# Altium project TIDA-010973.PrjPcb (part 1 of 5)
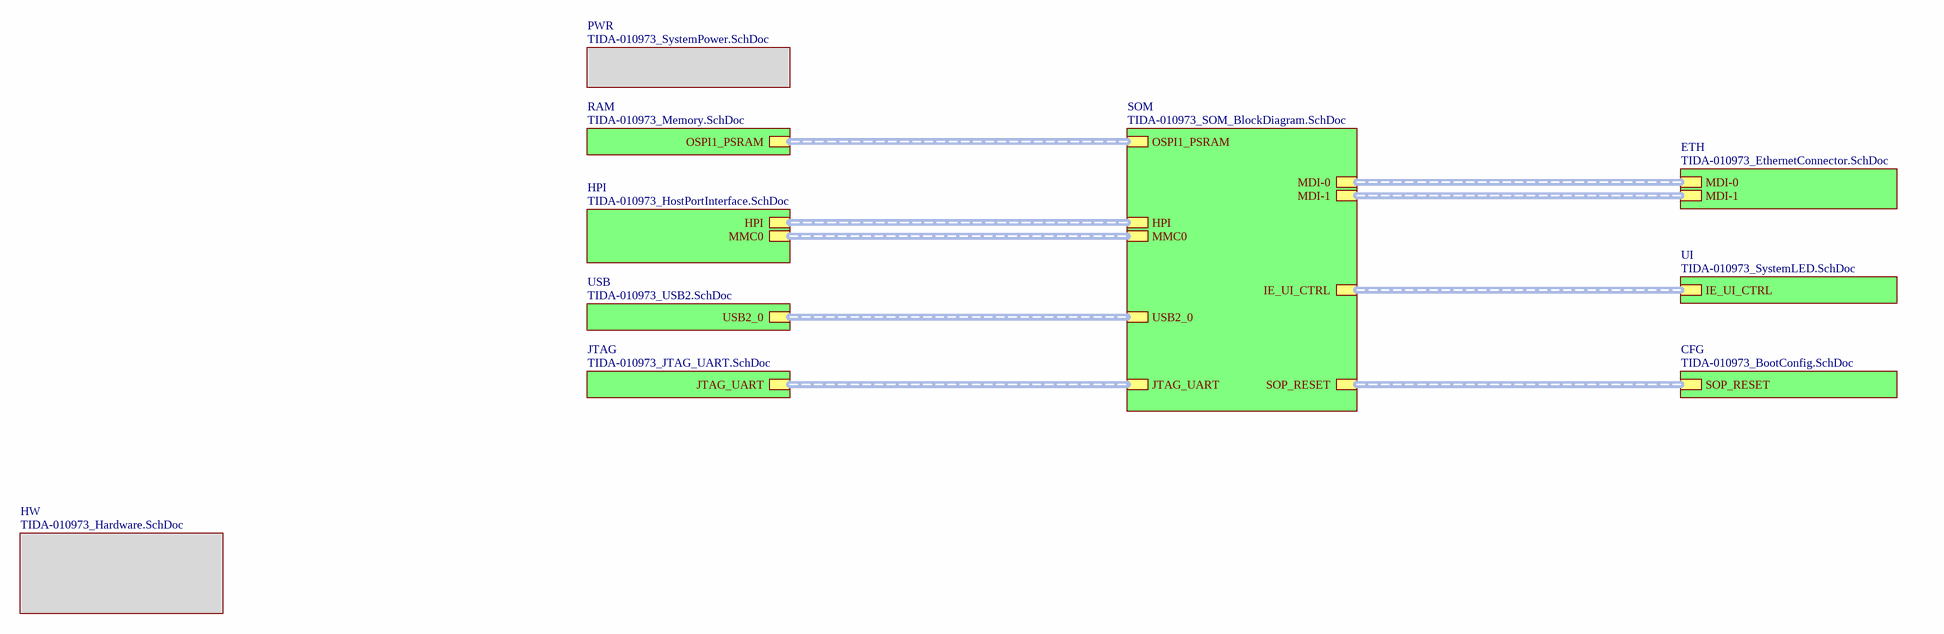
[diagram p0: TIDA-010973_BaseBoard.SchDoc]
CopyrightYear: 2025; PCB_Layout: Thomas Mauer; PCB_Rev: E1; PRJ_Customer: Public Release; PRJ_Engineer: Thomas Mauer; PRJ_Number: TIDA-010973; PRJ_Title: 100Mbit IE Comm Module; SCH_Rev: E1; TechSupport: http://www.ti.com/support; TID: TIDA-010973
15 sheets, 679 parts. Net scope: hierarchical (ports join the sheet entries above them; power ports are global).
Board file: TIDA-010973E1.PcbDoc
Sheets:
  TIDA-010973_BaseBoard.SchDoc
    ETH = TIDA-010973_EthernetConnector.SchDoc
    HPI = TIDA-010973_HostPortInterface.SchDoc
    SOM = TIDA-010973_SOM_BlockDiagram.SchDoc
      SOM-MEM = TIDA-010973_SOM-Memory.SchDoc
      SOM-ETH1 = TIDA-010973_SOM_Ethernet.SchDoc
      SOM-Power = TIDA-010973_SOM_PMIC.SchDoc
      SOM-MCU = TIDA-010973_SOM_MCU.SchDoc
      SOM-ETH2 = TIDA-010973_SOM_Ethernet.SchDoc
    PWR = TIDA-010973_SystemPower.SchDoc
    UI = TIDA-010973_SystemLED.SchDoc
    USB = TIDA-010973_USB2.SchDoc
    JTAG = TIDA-010973_JTAG_UART.SchDoc
    RAM = TIDA-010973_Memory.SchDoc
    CFG = TIDA-010973_BootConfig.SchDoc
    HW = TIDA-010973_Hardware.SchDoc

## Sheet TIDA-010973_BaseBoard.SchDoc
size 431 x 279 mm; Date: Not shown in title block; ApprovedBy: Not shown in title block; CheckedBy: Not shown in title block; Author: Not shown in title block; CompanyName: Not shown in title block; Engineer: Not shown in title block; Organization: Not shown in title block; Address1: Not shown in title block; Address2: Not shown in title block; Address3: Not shown in title block; Address4: Not shown in title block; DocumentNumber: 2; Revision: Use project parameter SCH_Rev; SheetNumber: 1; SheetTotal: 16; PageSetup: Record=PageOptions¦CenterHorizontal=True¦CenterVertical=True¦PrintScale=1.00¦XCorrection=1.00¦YCorrection=1.00¦PrintKind=0¦BorderSize=5000000¦LeftOffset=0¦BottomOffset=0¦Orientation=2¦PaperLength=1000¦PaperWidth=1000¦Scale=100¦PaperSource=15¦PrintQuality=600¦MediaType=1¦DitherType=10¦PaperKind=Letter¦PrintScaleMode=1

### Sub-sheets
CFG = TIDA-010973_BootConfig.SchDoc: SOP_RESET (harness SOP_RESET)
ETH = TIDA-010973_EthernetConnector.SchDoc: MDI-0 (harness MDI), MDI-1 (harness MDI)
HPI = TIDA-010973_HostPortInterface.SchDoc: HPI (harness HPI), MMC0 (harness MMC)
HW = TIDA-010973_Hardware.SchDoc: no entries
JTAG = TIDA-010973_JTAG_UART.SchDoc: JTAG_UART (harness JTAG_UART)
PWR = TIDA-010973_SystemPower.SchDoc: no entries
RAM = TIDA-010973_Memory.SchDoc: OSPI1_PSRAM (harness OSPI)
SOM = TIDA-010973_SOM_BlockDiagram.SchDoc: USB2_0 (harness USB2_0), OSPI1_PSRAM (harness OSPI), MDI-0 (harness MDI), MDI-1 (harness MDI), IE_UI_CTRL (harness IE_UI_CTRL), HPI (harness HPI), MMC0 (harness MMC), SOP_RESET (harness SOP_RESET), JTAG_UART (harness JTAG_UART)
UI = TIDA-010973_SystemLED.SchDoc: IE_UI_CTRL (harness IE_UI_CTRL)
USB = TIDA-010973_USB2.SchDoc: USB2_0 (harness USB2_0)

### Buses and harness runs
harness sheet CFG/SOP_RESET = sheet SOM/SOP_RESET
harness sheet ETH/MDI-0 = sheet SOM/MDI-0
harness sheet ETH/MDI-1 = sheet SOM/MDI-1
harness sheet HPI/HPI = sheet SOM/HPI
harness sheet HPI/MMC0 = sheet SOM/MMC0
harness sheet JTAG/JTAG_UART = sheet SOM/JTAG_UART
harness sheet RAM/OSPI1_PSRAM = sheet SOM/OSPI1_PSRAM
harness sheet SOM/IE_UI_CTRL = sheet UI/IE_UI_CTRL
harness sheet SOM/USB2_0 = sheet USB/USB2_0

## Sheet TIDA-010973_EthernetConnector.SchDoc
size 431 x 279 mm; Date: Not shown in title block; ApprovedBy: Not shown in title block; CheckedBy: Not shown in title block; Author: Not shown in title block; CompanyName: Not shown in title block; Engineer: Not shown in title block; Organization: Not shown in title block; Address1: Not shown in title block; Address2: Not shown in title block; Address3: Not shown in title block; Address4: Not shown in title block; DocumentNumber: 2; Revision: Use project parameter SCH_Rev; SheetNumber: 9; SheetTotal: 15; PageSetup: Record=PageOptions¦CenterHorizontal=True¦CenterVertical=True¦PrintScale=1.00¦XCorrection=1.00¦YCorrection=1.00¦PrintKind=0¦BorderSize=5000000¦LeftOffset=0¦BottomOffset=0¦Orientation=2¦PaperLength=1000¦PaperWidth=1000¦Scale=100¦PaperSource=15¦PrintQuality=600¦MediaType=1¦DitherType=10¦PaperKind=Letter¦PrintScaleMode=1
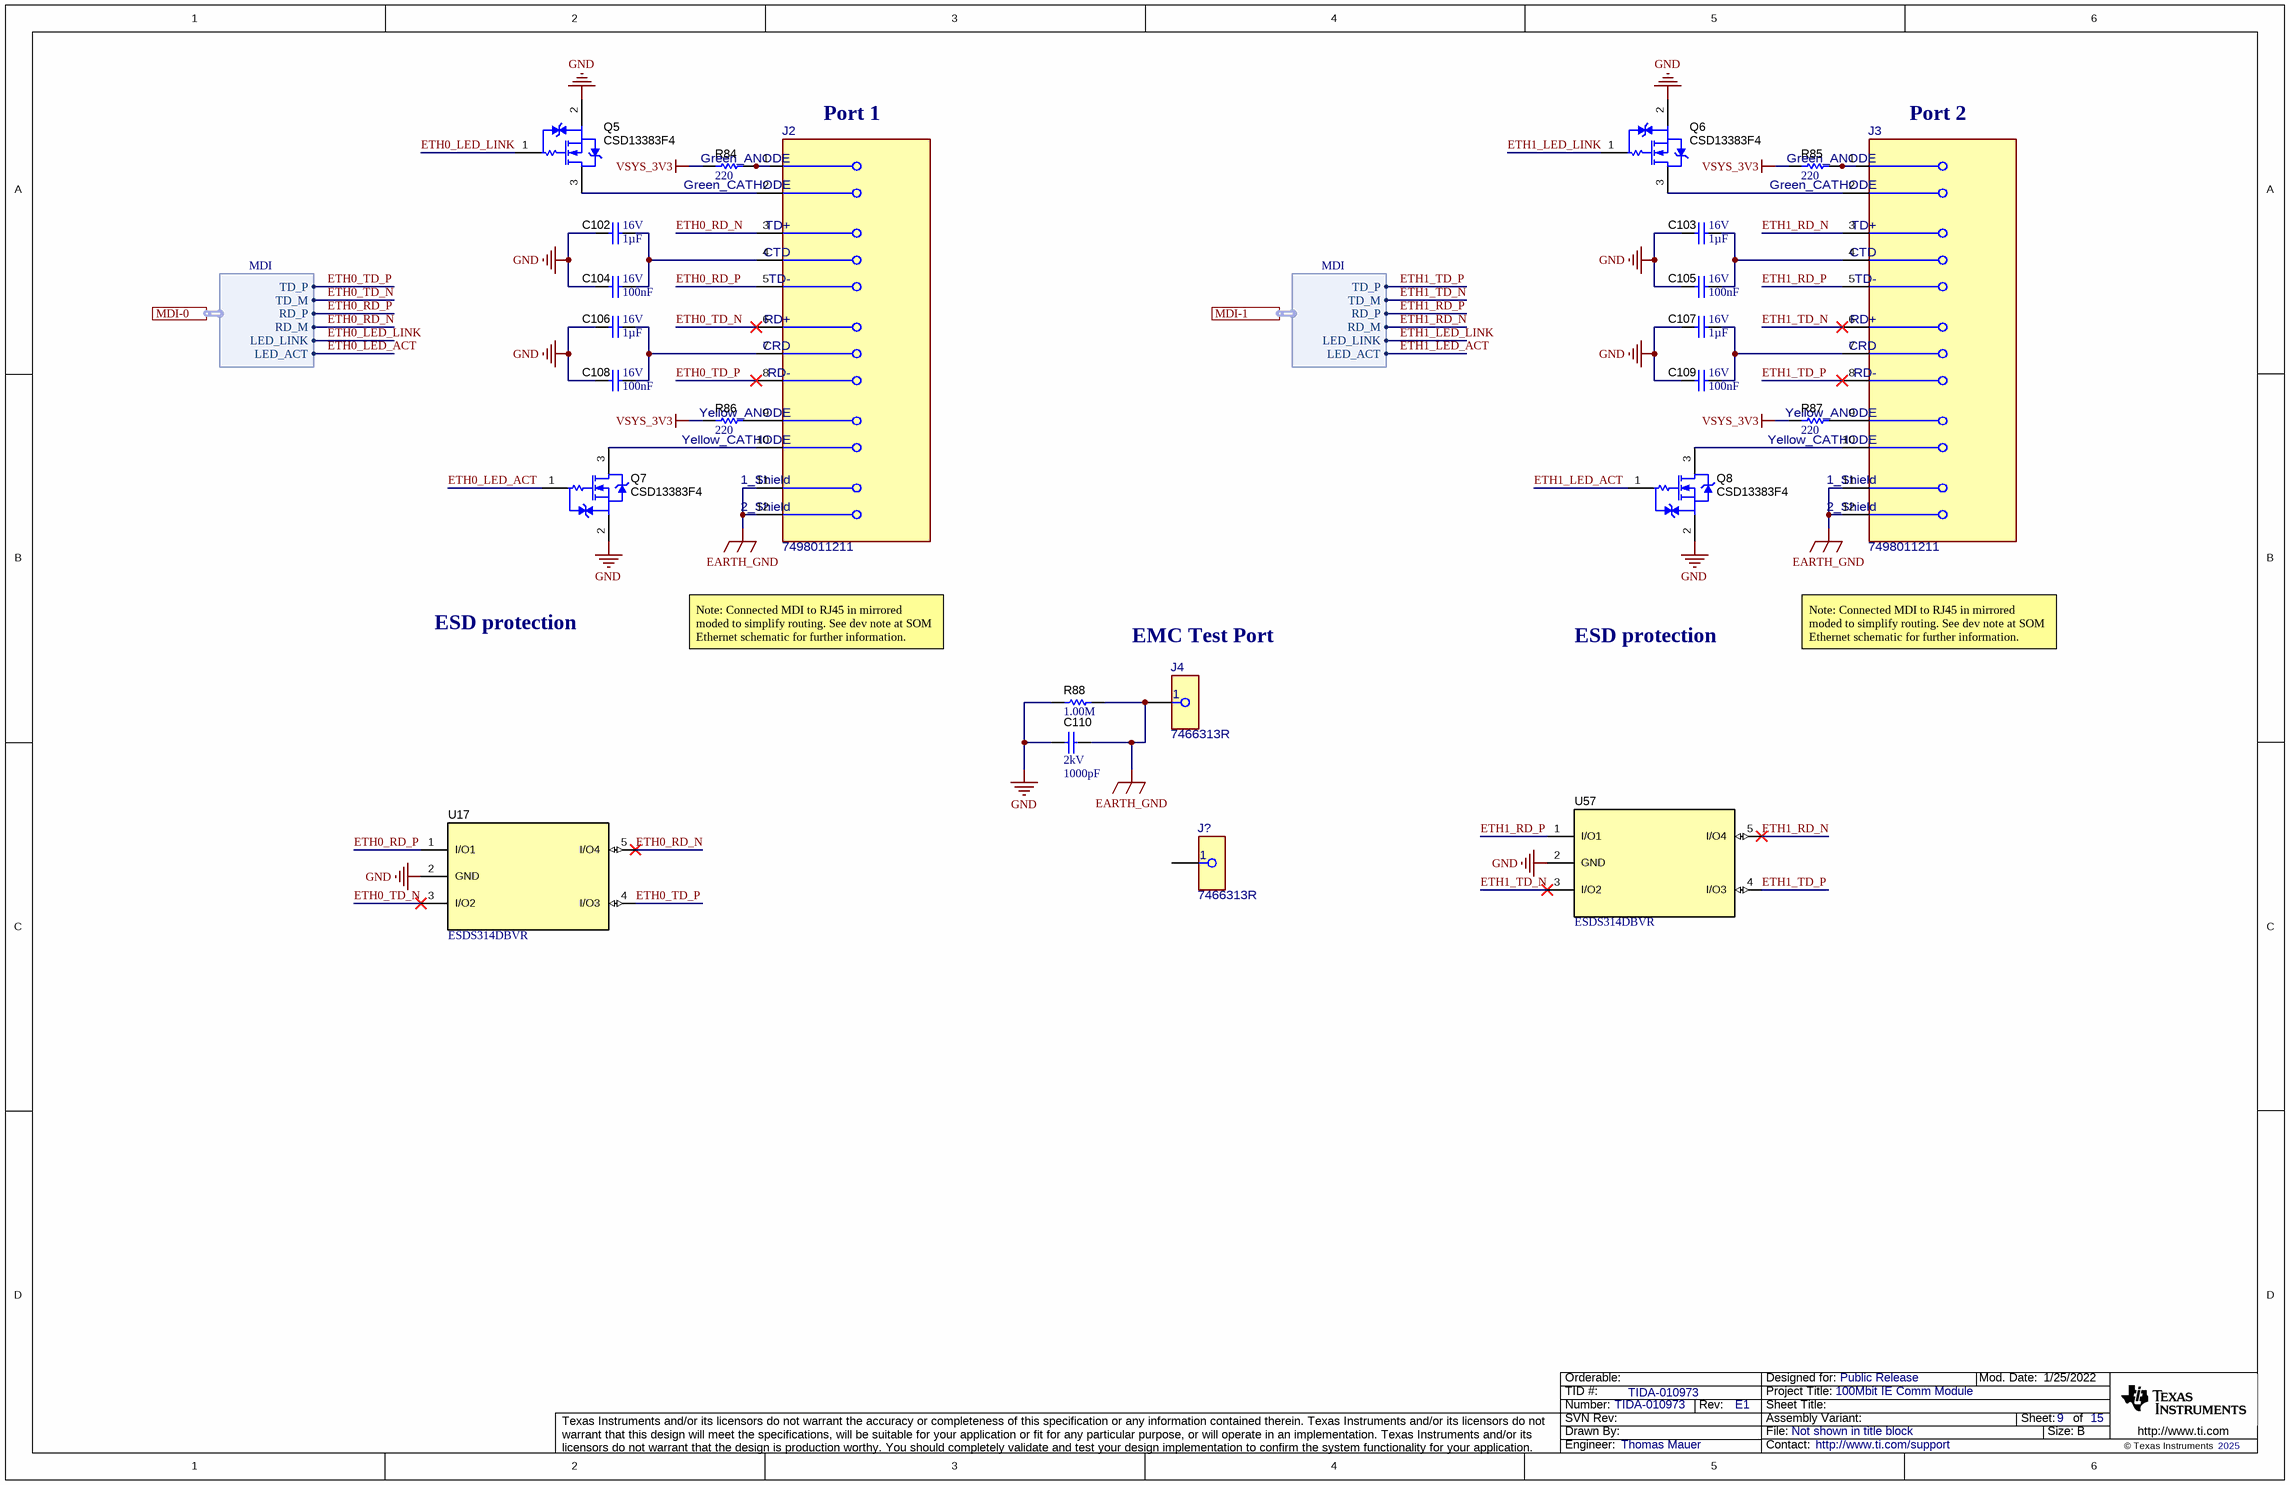
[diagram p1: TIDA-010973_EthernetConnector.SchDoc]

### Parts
C102  Cap_F: 1µF  VDC_V: 16V  [0603L]  (hidden comment: 885012206052)
C103  Cap_F: 1µF  VDC_V: 16V  [0603L]  (hidden comment: 885012206052)
C104  Cap_F: 100nF  VDC_V: 16V  [0603L]  (hidden comment: 885012206046)
C105  Cap_F: 100nF  VDC_V: 16V  [0603L]  (hidden comment: 885012206046)
C106  Cap_F: 1µF  VDC_V: 16V  [0603L]  (hidden comment: 885012206052)
C107  Cap_F: 1µF  VDC_V: 16V  [0603L]  (hidden comment: 885012206052)
C108  Cap_F: 100nF  VDC_V: 16V  [0603L]  (hidden comment: 885012206046)
C109  Cap_F: 100nF  VDC_V: 16V  [0603L]  (hidden comment: 885012206046)
C110  VDC_V: 2kV  ValueDisplayed: 1000pF  [1812_254]  (hidden comment: 1812GC102KA1)
J2  7498011211  [FP-7498011211_RJ45MAG-MFG]
J3  7498011211  [FP-7498011211_RJ45MAG-MFG]
J4  7466313R  [FP-7466313R_SMT_REDCUBE_7MM00_4MM33-MFG]
J?  7466313R  [FP-7466313R_SMT_REDCUBE_7MM00_4MM33-MFG]
Q5  CSD13383F4  [YJC0003A]
Q6  CSD13383F4  [YJC0003A]
Q7  CSD13383F4  [YJC0003A]
Q8  CSD13383F4  [YJC0003A]
R84  ValueDisplayed: 220  [0402L]  (hidden comment: CRCW0402220RJNTD)
R85  ValueDisplayed: 220  [0402L]  (hidden comment: CRCW0402220RJNTD)
R86  ValueDisplayed: 220  [0402L]  (hidden comment: CRCW0402220RJNTD)
R87  ValueDisplayed: 220  [0402L]  (hidden comment: CRCW0402220RJNTD)
R88  ValueDisplayed: 1.00M  [2010]  (hidden comment: CRCW20101M00FKEF)
U17  ESDS314DBVR  [DBV0005A_N]
U57  ESDS314DBVR  [DBV0005A_N]

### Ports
MDI-0 (harness MDI), MDI-1 (harness MDI)

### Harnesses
MDI: TD_M, RD_P, RD_M, LED_LINK, TD_P, LED_ACT

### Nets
EARTH_GND: C110.1 J2.11(1_Shield) J2.12(2_Shield) J3.11(1_Shield) J3.12(2_Shield) J4.1 R88.2
GND: C102.2 C103.2 C104.2 C105.2 C106.2 C107.2 C108.2 C109.2 C110.2 Q5.2(S) Q6.2(S) Q7.2(S) Q8.2(S) R88.1 U17.2(GND) U57.2(GND)
VSYS_3V3: R84.2 R85.2 R86.2 R87.2
ETH0_LED_ACT: Q7.1(G) ; port MDI-0.LED_ACT
ETH0_LED_LINK: Q5.1(G) ; port MDI-0.LED_LINK
ETH0_RD_N: J2.3(TD+) U17.5(I/O4) ; port MDI-0.RD_M
ETH0_RD_P: J2.5(TD-) U17.1(I/O1) ; port MDI-0.RD_P
ETH0_TD_N: J2.6(RD+) U17.3(I/O2) ; port MDI-0.TD_M
ETH0_TD_P: J2.8(RD-) U17.4(I/O3) ; port MDI-0.TD_P
ETH1_LED_ACT: Q8.1(G) ; port MDI-1.LED_ACT
ETH1_LED_LINK: Q6.1(G) ; port MDI-1.LED_LINK
ETH1_RD_N: J3.3(TD+) U57.5(I/O4) ; port MDI-1.RD_M
ETH1_RD_P: J3.5(TD-) U57.1(I/O1) ; port MDI-1.RD_P
ETH1_TD_N: J3.6(RD+) U57.3(I/O2) ; port MDI-1.TD_M
ETH1_TD_P: J3.8(RD-) U57.4(I/O3) ; port MDI-1.TD_P
NetC102_1: C102.1 C104.1 J2.4(CTD)
NetC103_1: C103.1 C105.1 J3.4(CTD)
NetC106_1: C106.1 C108.1 J2.7(CRD)
NetC107_1: C107.1 C109.1 J3.7(CRD)
NetJ2_1: J2.1(Green_ANODE) R84.1
NetJ2_2: J2.2(Green_CATHODE) Q5.3(D)
NetJ2_9: J2.9(Yellow_ANODE) R86.1
NetJ2_10: J2.10(Yellow_CATHODE) Q7.3(D)
NetJ3_1: J3.1(Green_ANODE) R85.1
NetJ3_2: J3.2(Green_CATHODE) Q6.3(D)
NetJ3_9: J3.9(Yellow_ANODE) R87.1
NetJ3_10: J3.10(Yellow_CATHODE) Q8.3(D)

Not connected (* = marked no-connect by the designer): J? 1

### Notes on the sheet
- Port 1
- Port 2
- ESD protection
- Note: Connected MDI to RJ45 in mirrored moded to simplify routing. See dev note at SOM Ethernet schematic for further information.
- EMC Test Port

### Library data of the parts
C102 C103 C106 C107 = CMP-0006831-4: CAP, CERM, 1 uF, 16 V, +/- 10%, X7R, 0603; Manufacturer: Wurth Elektronik; TaMin_C: -55°C; Polarized: N; SizeAreaWB_mm2: 4.68; Value1: Unknown; U/M: EA; Value: 1uF; TaMax_C: 125°C; SizeZ_mm: 1; SizeX_mm: 1.6; SizeY_mm: 0.8; Cap_Case: 0603; SizeArea_mm2: 1.28; AEC Category: Q200
C104 C105 C108 C109 = CMP-0006829-4: CAP, CERM, 0.1 uF, 16 V, +/- 10%, X7R, 0603; Manufacturer: Wurth Elektronik; TaMin_C: -55°C; Polarized: N; SizeAreaWB_mm2: 4.68; Value1: Unknown; U/M: EA; Value: 0.1uF; TaMax_C: 125°C; SizeZ_mm: 1; SizeX_mm: 1.6; SizeY_mm: 0.8; Cap_Case: 0603; SizeArea_mm2: 1.28; AEC Category: Q200
C110 = CMP-0009293-2: CAP, CERM, 1000 pF, 2000 V, +/- 10%, X7R, 1812; Manufacturer: AVX; TaMin_C: -55°C; Polarized: N; SizeAreaWB_mm2: 23.1; Value1: Unknown; U/M: EA; Value: 1000pF; TaMax_C: 125°C; SizeZ_mm: 2.54; SizeX_mm: 4.5; SizeY_mm: 3.2; Cap_Case: 1812; Value2: 2000V; SizeArea_mm2: 14.4; Cap_F: 1nF; AEC Category: Q200
J2 J3 = CMP-0065699-1: 1 Port RJ45Surface Mount 10/100 Base-T, AutoMDIX; Manufacturer: Wurth Electronics; ContactFinish: Gold,Nickel; Shrouded: true; AEC Qualified: No; Conn Gender: Female; Conn Orientation: Right Angle; DUT-Pitch_mm: 1.27mm; Is Female: yes; SizeZ_mm: 13.8mm
J4 J? = CMP-0043004-2: 2 Pin Screw Terminal, Power Tap M3 Surface Mount, Right Angle; Manufacturer: Wurth Electronics; ContactFinish: Tin; Current_A: 50A; AEC Qualified: No; Conn Gender: Female; Is Female: yes; SizeZ_mm: 7.2mm
Q5-Q8 = CMP-0000198-1: MOSFET, N-CH, 12 V, 2.9 A, YJC0003A (PICOSTAR-3); Alternate Manufacturer: None; Manufacturer: Texas Instruments; SizeZ_mm: 0.35; ChType: N; Value2: 2 nC; Value1: 0.04; VdsMax_V: 12V; SizeX_mm: 1.035; SizeY_mm: 0.635; Vgs_V: 10V; Value: 12V; Rdson45_ohm: 0.044; SizeArea_mm2: 0.657225; AEC Category: Q101; IdsMax_A: 2.9A; SizeAreaWB_mm2: 3.327225; U/M: EA; QgTyp_nC: 2
R84-R87 = CMP-0081786-1: RES, 220, 5%, 0.063 W, AEC-Q200 Grade 0, 0402; Manufacturer: Vishay-Dale; Power_W: 63mW; TempCo: 200 ppm/C; SizeAreaWB_mm2: 3; Value_Code: 220R; Value: 220; EIA_Code: E24; SizeX_mm: 1; SizeY_mm: 0.5; SizeZ_mm: 0.6; Value2: 0.063W; AEC Qualified: Y; VDC_V: 50V; AEC Grade: 0; AEC Category: Q200
R88 = CMP-0016296-3: RES, 1.00 M, 1%, 0.75 W, AEC-Q200 Grade 0, 2010; Manufacturer: Vishay-Dale; Power_W: 750mW; TempCo: 100 ppm/C; Value_Code: 1M00; Value: 1.00Meg; EIA_Code: E96; Res_ohm: 1M; SizeX_mm: 5; SizeY_mm: 2.5; SizeZ_mm: 1.66; Value2: 0.75W; SizeArea_mm2: 12.5; AEC Qualified: Y; VDC_V: 400V; AEC Grade: 0; AEC Category: Q200
U17 U57 = CMP-0085635-1: Data-Line Surge and ESD Protection Diode Array, DBV0005A (SOT-23-5); Alternate Manufacturer: Texas Instruments; CompType: IC; SizeX_mm: 2.8; Rating: Catalog; AEC Category: Q200; SizeZ_mm: 1.45; SizeArea_mm2: 8.12; AEC Qualified: N; SizeAreaWB_mm2: 14.82; SizeY_mm: 2.9

## Sheet TIDA-010973_HostPortInterface.SchDoc
size 558 x 431 mm; Date: Not shown in title block; ApprovedBy: Not shown in title block; CheckedBy: Not shown in title block; Author: Not shown in title block; CompanyName: Not shown in title block; Engineer: Not shown in title block; Organization: Not shown in title block; Address1: Not shown in title block; Address2: Not shown in title block; Address3: Not shown in title block; Address4: Not shown in title block; DocumentNumber: 2; Revision: Use project parameter SCH_Rev; SheetNumber: 11; SheetTotal: 15; PageSetup: Record=PageOptions¦CenterHorizontal=True¦CenterVertical=True¦PrintScale=1.00¦XCorrection=1.00¦YCorrection=1.00¦PrintKind=0¦BorderSize=5000000¦LeftOffset=0¦BottomOffset=0¦Orientation=2¦PaperLength=1000¦PaperWidth=1000¦Scale=100¦PaperSource=15¦PrintQuality=600¦MediaType=1¦DitherType=10¦PaperKind=Letter¦PrintScaleMode=1
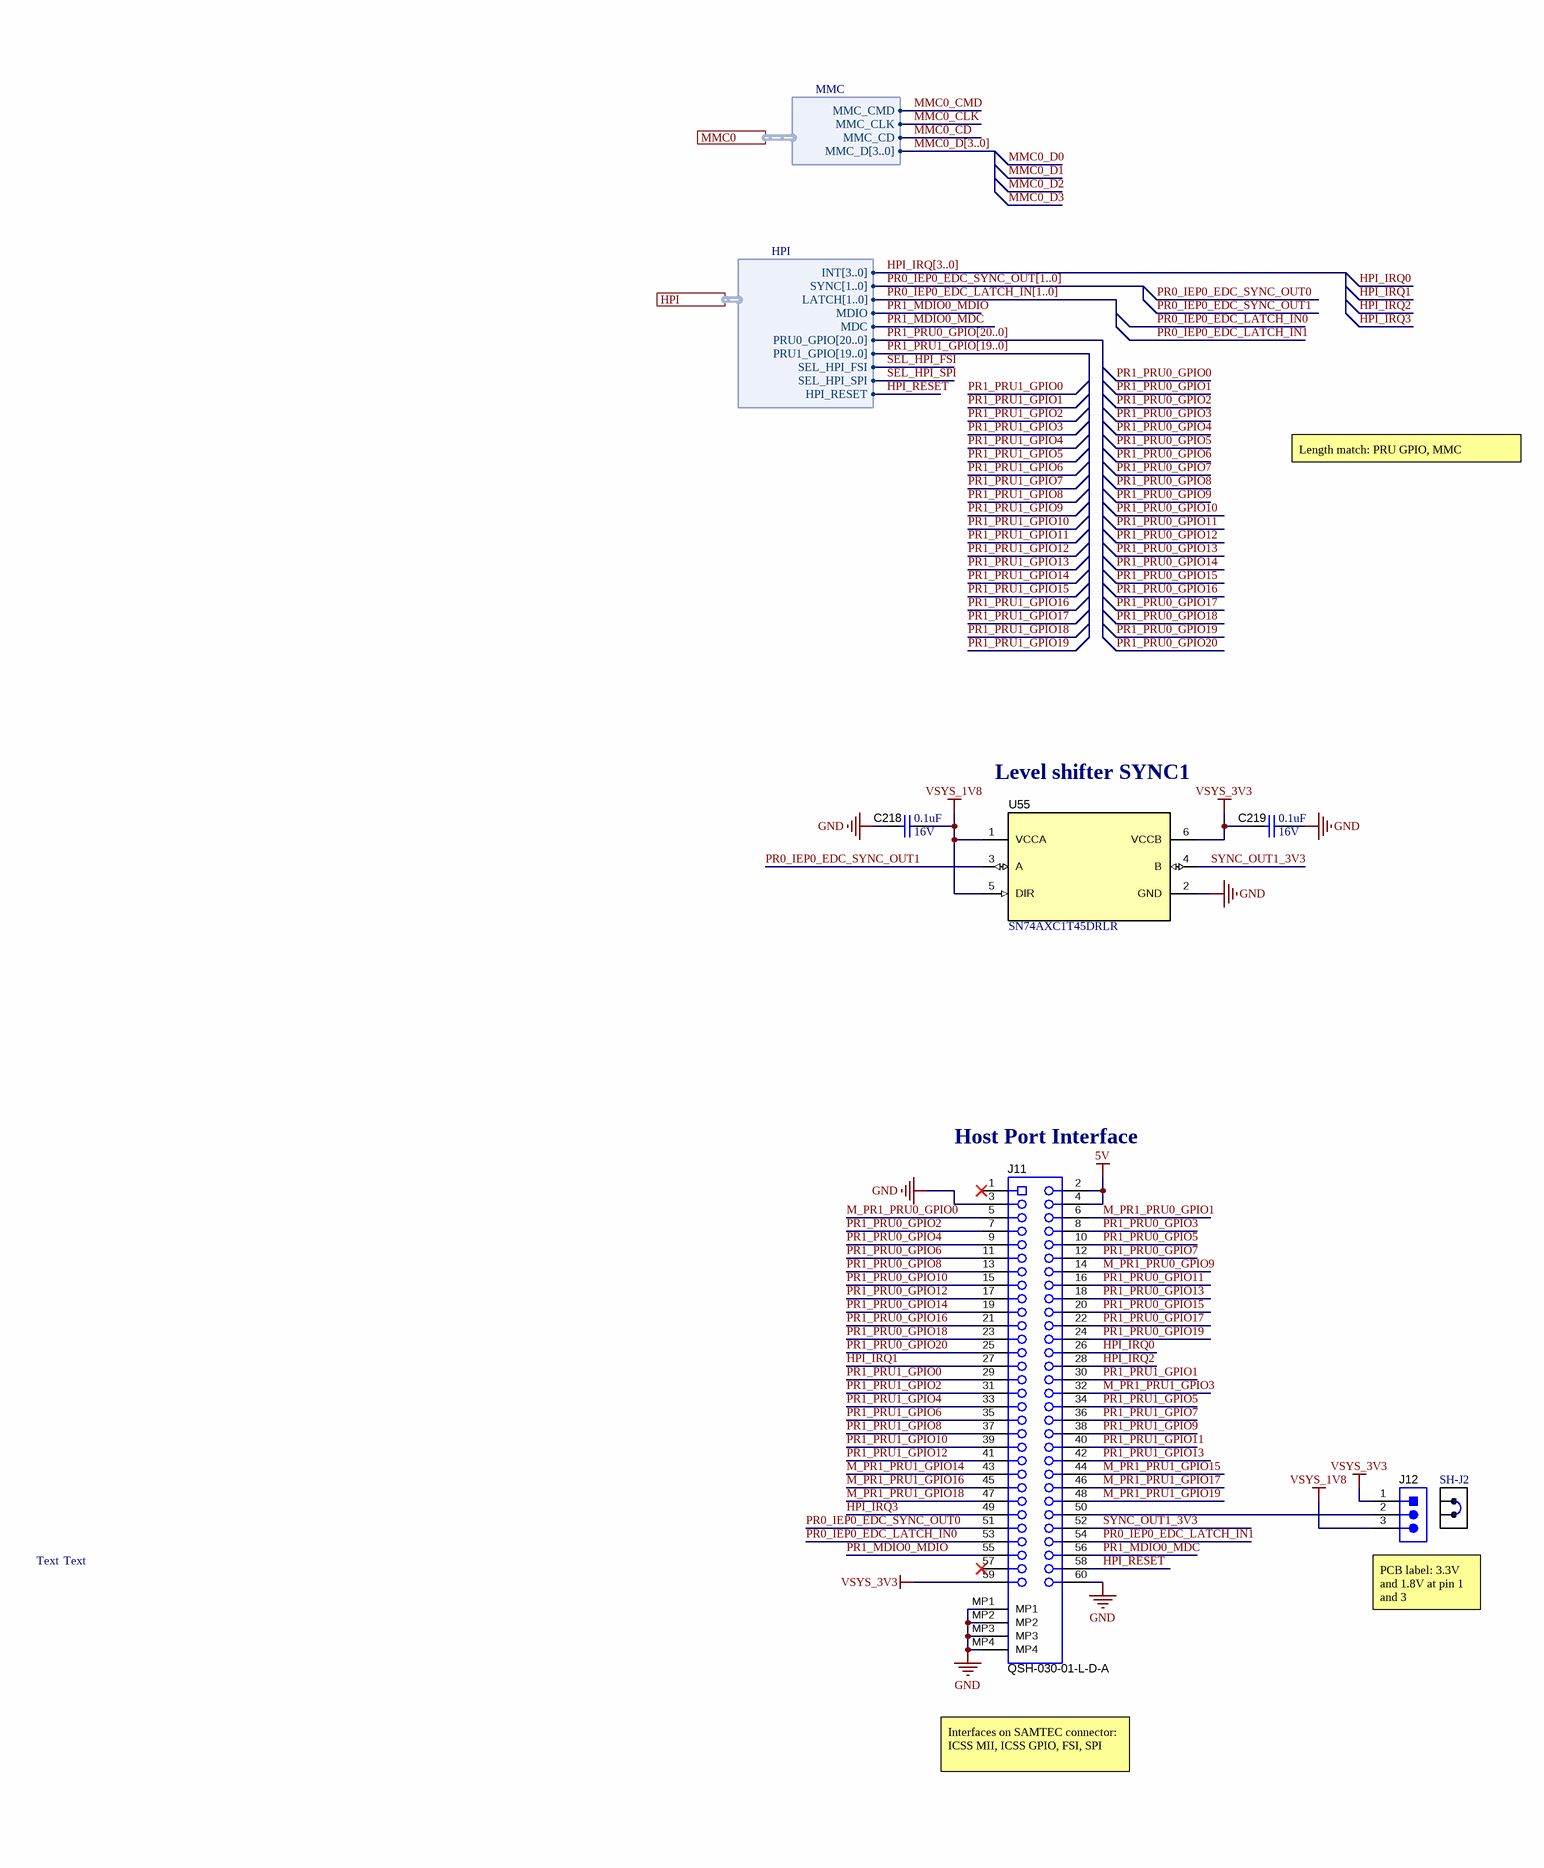
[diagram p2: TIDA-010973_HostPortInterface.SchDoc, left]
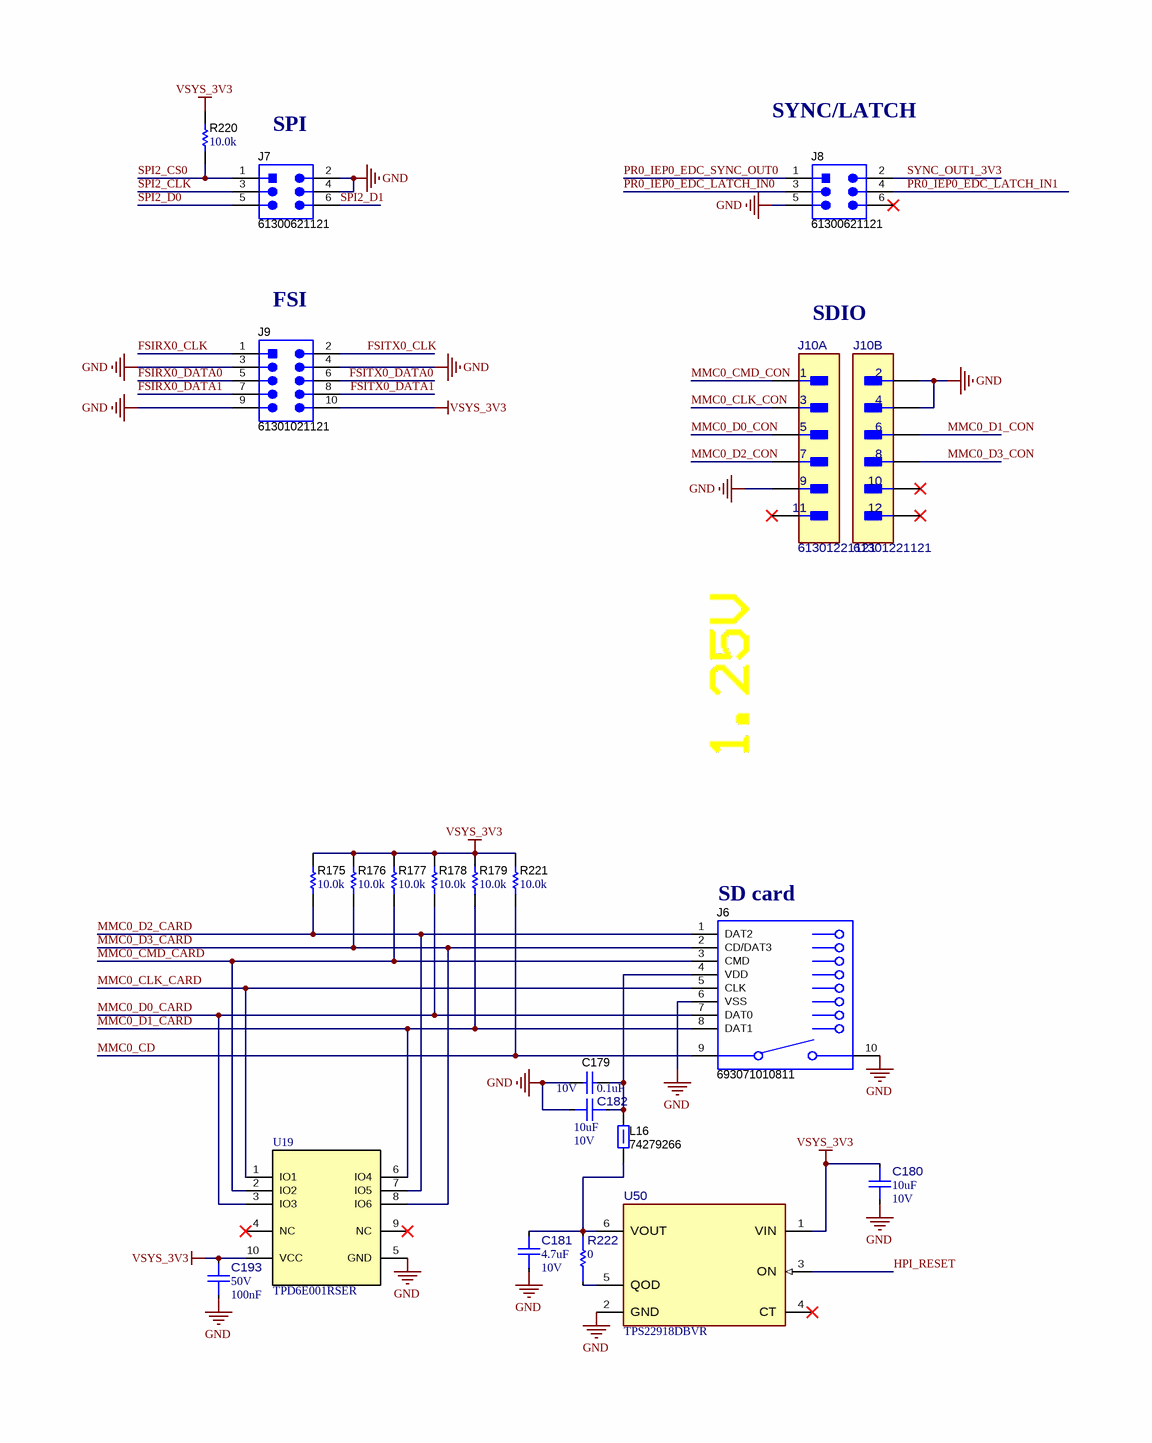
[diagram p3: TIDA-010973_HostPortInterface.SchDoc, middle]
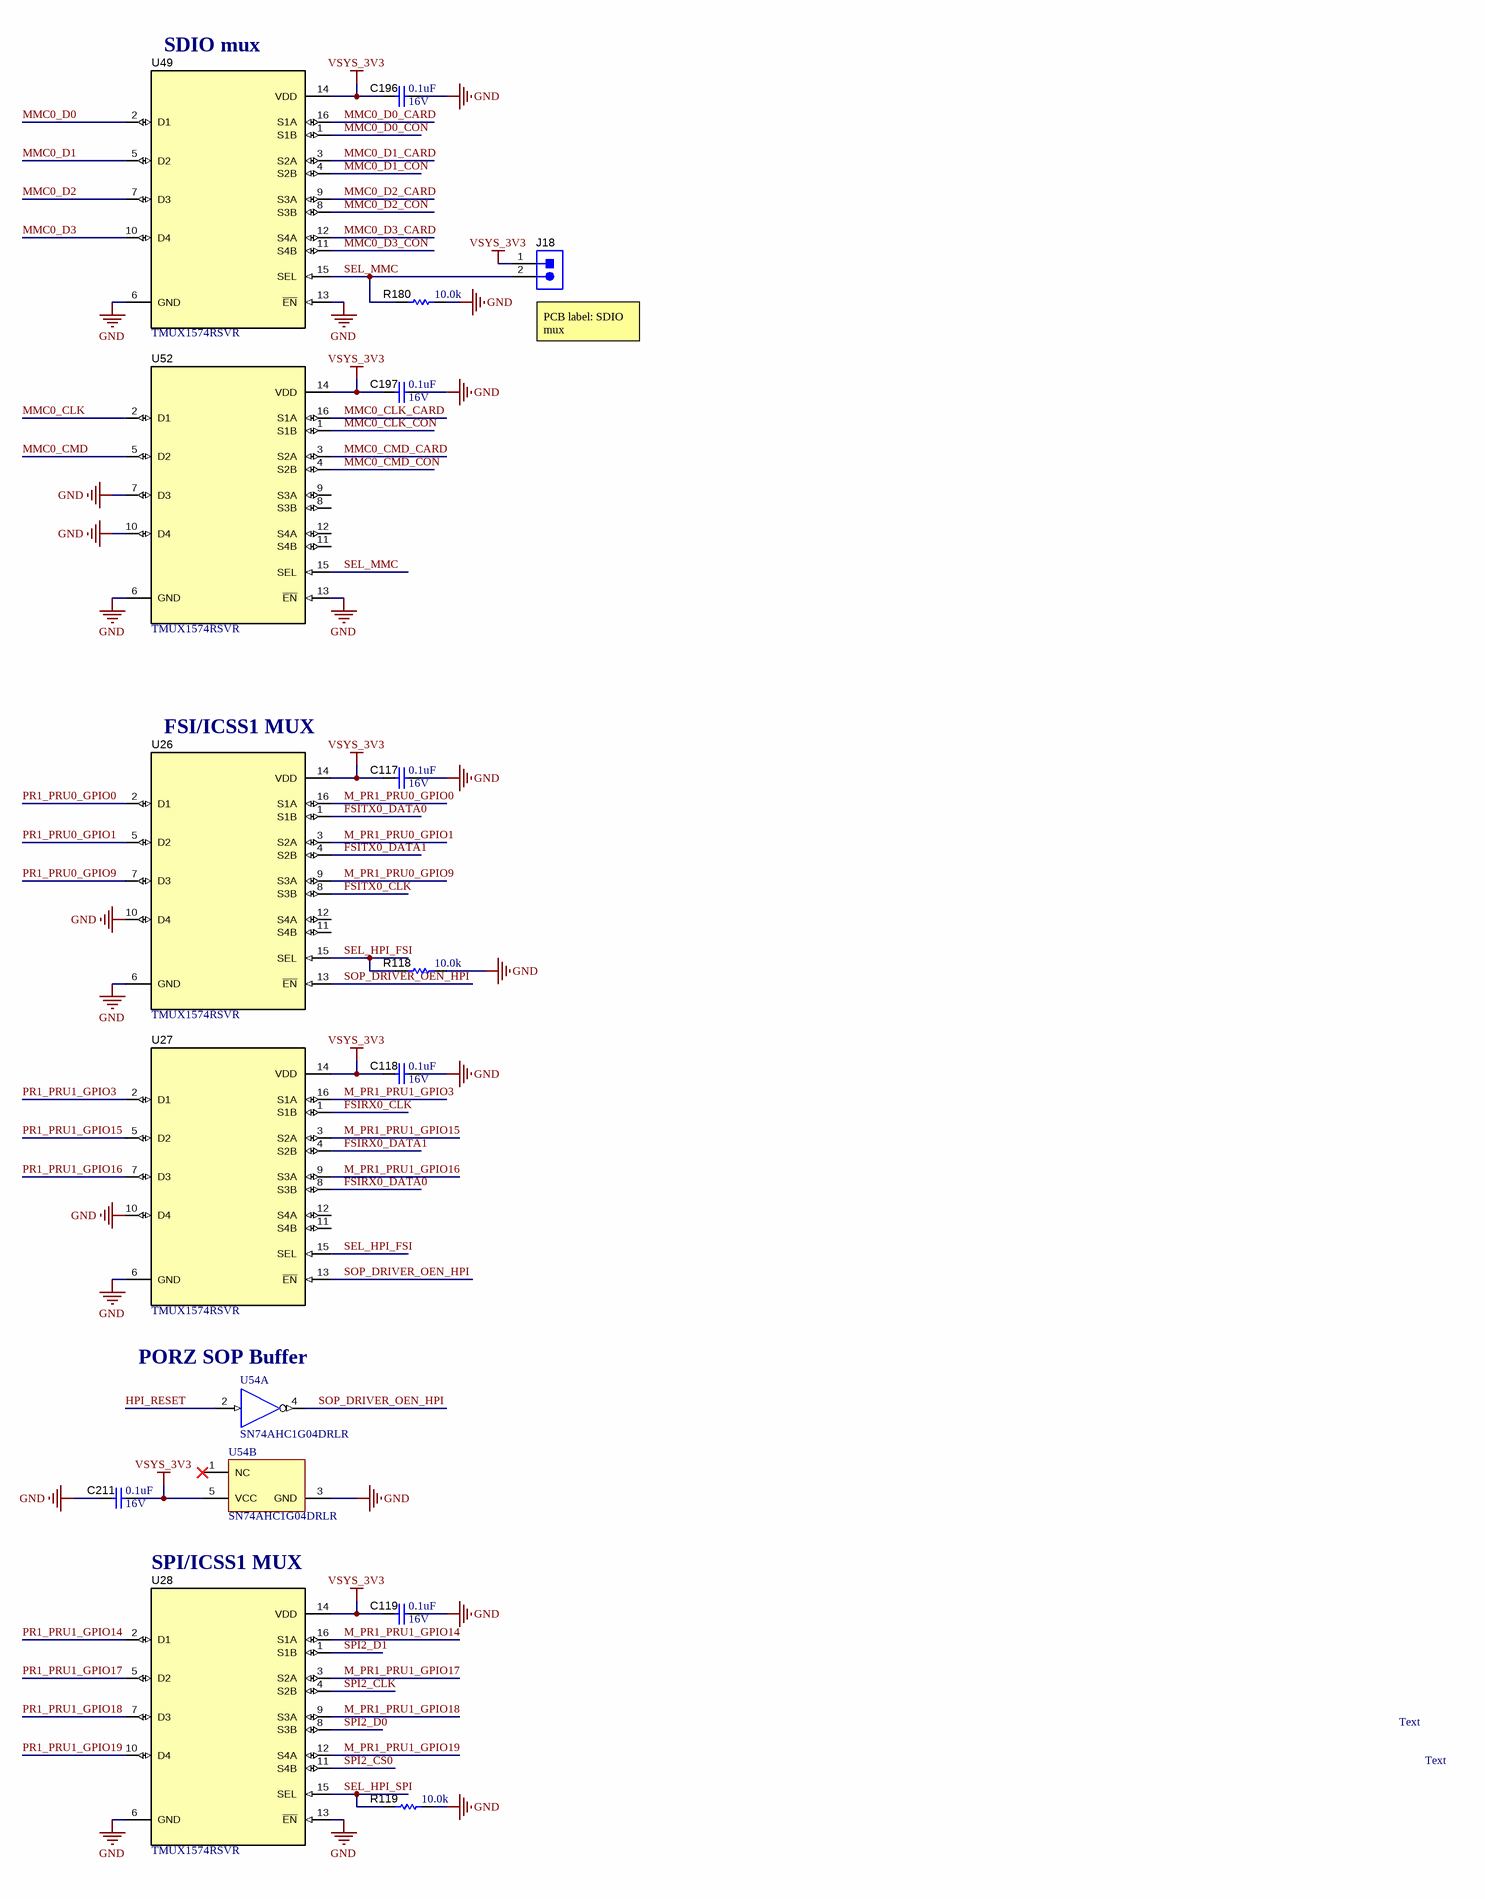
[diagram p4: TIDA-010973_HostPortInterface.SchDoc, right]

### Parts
C117  VDC_V: 16V  ValueDisplayed: 0.1uF  [0402L]  (hidden comment: 885012205037)
C118  VDC_V: 16V  ValueDisplayed: 0.1uF  [0402L]  (hidden comment: 885012205037)
C119  VDC_V: 16V  ValueDisplayed: 0.1uF  [0402L]  (hidden comment: 885012205037)
C179  VDC_V: 10V  ValueDisplayed: 0.1uF  [0402L]  (hidden comment: 885012105010)
C180  ValueDisplayed: 10uF  VDC_V: 10V  [FP-GRM155R61A106ME18D_0402-IPC_C]  (hidden comment: GRM155R61A106ME18D)
C181  ValueDisplayed: 4.7uF  VDC_V: 10V  [FP-885012106012_0603-IPC_C]  (hidden comment: 885012106012)
C182  ValueDisplayed: 10uF  VDC_V: 10V  [FP-GRM155R61A106ME18D_0402-IPC_C]  (hidden comment: GRM155R61A106ME18D)
C193  VDC_V: 50V  ValueDisplayed: 100nF  [FP-885012205086_0402-IPC_C]  (hidden comment: 885012205086)
C196  VDC_V: 16V  ValueDisplayed: 0.1uF  [0402L]  (hidden comment: 885012205037)
C197  VDC_V: 16V  ValueDisplayed: 0.1uF  [0402L]  (hidden comment: 885012205037)
C211  VDC_V: 16V  ValueDisplayed: 0.1uF  [0402L]  (hidden comment: 885012205037)
C218  VDC_V: 16V  ValueDisplayed: 0.1uF  [0402L]  (hidden comment: 885012205037)
C219  VDC_V: 16V  ValueDisplayed: 0.1uF  [0402L]  (hidden comment: 885012205037)
J6  693071010811  [Molex_693071010811]
J7  61300621121  [Wurth_61300621121]
J8  61300621121  [Wurth_61300621121]
J9  61301021121  [WURTH_61301021121]
J10  61301221121  [FP-61301221121_HDR12-MFG]  (parts A,B of 2)
J11  QSH-030-01-L-D-A  [Samtec_QSH-030-01-X-D-A]
J12  61300311121  [WURTH_61300311121]  (value not drawn)
J18  61300211121  [WURTH_61300211121]  (value not drawn)
L16  74279266  [0603L]
R118  ValueDisplayed: 10.0k  [0402L]  (hidden comment: CRCW040210K0FKED)
R119  ValueDisplayed: 10.0k  [0402L]  (hidden comment: CRCW040210K0FKED)
R175  ValueDisplayed: 10.0k  [0402L]  (hidden comment: CRCW040210K0FKED)
R176  ValueDisplayed: 10.0k  [0402L]  (hidden comment: CRCW040210K0FKED)
R177  ValueDisplayed: 10.0k  [0402L]  (hidden comment: CRCW040210K0FKED)
R178  ValueDisplayed: 10.0k  [0402L]  (hidden comment: CRCW040210K0FKED)
R179  ValueDisplayed: 10.0k  [0402L]  (hidden comment: CRCW040210K0FKED)
R180  ValueDisplayed: 10.0k  [0402L]  (hidden comment: CRCW040210K0FKED)
R220  ValueDisplayed: 10.0k  [0402L]  (hidden comment: CRCW040210K0FKED)
R221  ValueDisplayed: 10.0k  [0402L]  (hidden comment: CRCW040210K0FKED)
R222  value 0  [FP-CRCW04020000Z0EDC_0402-IPC_C]  (hidden comment: CRCW04020000Z0EDC)
SH-J2  60900213421  [Wurth_60900213421]  (value not drawn)
U19  TPD6E001RSER  [RSE0010A]
U26  TMUX1574RSVR  [RSV0016A]
U27  TMUX1574RSVR  [RSV0016A]
U28  TMUX1574RSVR  [RSV0016A]
U49  TMUX1574RSVR  [RSV0016A]
U50  TPS22918DBVR  [DBV0006A-IPC_C]
U52  TMUX1574RSVR  [RSV0016A]
U54  SN74AHC1G04DRLR  [DRL0005A]  (parts A,B of 2)
U55  SN74AXC1T45DRLR  [DRL0006A]

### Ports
HPI (harness HPI), MMC0 (harness MMC)

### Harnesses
HPI: SYNC[1..0], LATCH[1..0], INT[3..0], PRU0_GPIO[20..0], PRU1_GPIO[19..0], MDIO, MDC, SEL_HPI_SPI, SEL_HPI_FSI, HPI_RESET
MMC: MMC_CLK, MMC_CD, MMC_CMD, MMC_D[3..0]

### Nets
5V: J11.2 J11.4
GND: C117.2 C118.2 C119.2 C179.1 C180.2 C181.1 C182.2 C193.1 C196.2 C197.2 C211.1 C218.1 C219.2 J6.6(VSS) J6.10 J7.2 J7.4 J8.5 J9.3 J9.4 J9.9 J10.2 J10.4 J10.9 J11.3 J11.60 J11.MP1 J11.MP2 J11.MP3 J11.MP4 R118.1 R119.1 R180.1 U19.5(GND) U26.6(GND) U26.10(D4) U27.6(GND) U27.10(D4) U28.6(GND) U28.13(~{EN}) U49.6(GND) U49.13(~{EN}) U50.2(GND) U52.6(GND) U52.7(D3) U52.10(D4) U52.13(~{EN}) U54.3(GND) U55.2(GND)
VSYS_1V8: C218.2 J12.3 U55.1(VCCA) U55.5(DIR)
VSYS_3V3: C117.1 C118.1 C119.1 C180.1 C193.2 C196.1 C197.1 C211.2 C219.1 J9.10 J11.59 J12.1 J18.1 R175.2 R176.2 R177.2 R178.2 R179.2 R220.2 R221.2 U19.10(VCC) U26.14(VDD) U27.14(VDD) U28.14(VDD) U49.14(VDD) U50.1(VIN) U52.14(VDD) U54.5(VCC) U55.6(VCCB)
FSIRX0_CLK: J9.1 U27.1(S1B)
FSIRX0_DATA0: J9.5 U27.8(S3B)
FSIRX0_DATA1: J9.7 U27.4(S2B)
FSITX0_CLK: J9.2 U26.8(S3B)
FSITX0_DATA0: J9.6 U26.1(S1B)
FSITX0_DATA1: J9.8 U26.4(S2B)
HPI_IRQ0: J11.26
HPI_IRQ1: J11.27
HPI_IRQ2: J11.28
HPI_IRQ3: J11.49
HPI_RESET: J11.58 U50.3(ON) U54.2(A) ; port HPI.HPI_RESET
M_PR1_PRU0_GPIO0: J11.5 U26.16(S1A)
M_PR1_PRU0_GPIO1: J11.6 U26.3(S2A)
M_PR1_PRU0_GPIO9: J11.14 U26.9(S3A)
M_PR1_PRU1_GPIO3: J11.32 U27.16(S1A)
M_PR1_PRU1_GPIO14: J11.43 U28.16(S1A)
M_PR1_PRU1_GPIO15: J11.44 U27.3(S2A)
M_PR1_PRU1_GPIO16: J11.45 U27.9(S3A)
M_PR1_PRU1_GPIO17: J11.46 U28.3(S2A)
M_PR1_PRU1_GPIO18: J11.47 U28.9(S3A)
M_PR1_PRU1_GPIO19: J11.48 U28.12(S4A)
MMC0_CD: J6.9 R221.1 ; port MMC0.MMC_CD
MMC0_CLK: U52.2(D1) ; port MMC0.MMC_CLK
MMC0_CLK_CARD: J6.5(CLK) U19.1(IO1) U52.16(S1A)
MMC0_CLK_CON: J10.3 U52.1(S1B)
MMC0_CMD: U52.5(D2) ; port MMC0.MMC_CMD
MMC0_CMD_CARD: J6.3(CMD) R177.1 U19.2(IO2) U52.3(S2A)
MMC0_CMD_CON: J10.1 U52.4(S2B)
MMC0_D0: U49.2(D1)
MMC0_D0_CARD: J6.7(DAT0) R178.1 U19.3(IO3) U49.16(S1A)
MMC0_D0_CON: J10.5 U49.1(S1B)
MMC0_D1: U49.5(D2)
MMC0_D1_CARD: J6.8(DAT1) R179.1 U19.6(IO4) U49.3(S2A)
MMC0_D1_CON: J10.6 U49.4(S2B)
MMC0_D2: U49.7(D3)
MMC0_D2_CARD: J6.1(DAT2) R175.1 U19.7(IO5) U49.9(S3A)
MMC0_D2_CON: J10.7 U49.8(S3B)
MMC0_D3: U49.10(D4)
MMC0_D3_CARD: J6.2(CD/DAT3) R176.1 U19.8(IO6) U49.12(S4A)
MMC0_D3_CON: J10.8 U49.11(S4B)
PR0_IEP0_EDC_LATCH_IN0: J8.3 J11.53
PR0_IEP0_EDC_LATCH_IN1: J8.4 J11.54
PR0_IEP0_EDC_SYNC_OUT0: J8.1 J11.51
PR0_IEP0_EDC_SYNC_OUT1: U55.3(A)
PR1_MDIO0_MDC: J11.56 ; port HPI.MDC
PR1_MDIO0_MDIO: J11.55 ; port HPI.MDIO
PR1_PRU0_GPIO0: U26.2(D1)
PR1_PRU0_GPIO1: U26.5(D2)
PR1_PRU0_GPIO2: J11.7
PR1_PRU0_GPIO3: J11.8
PR1_PRU0_GPIO4: J11.9
PR1_PRU0_GPIO5: J11.10
PR1_PRU0_GPIO6: J11.11
PR1_PRU0_GPIO7: J11.12
PR1_PRU0_GPIO8: J11.13
PR1_PRU0_GPIO9: U26.7(D3)
PR1_PRU0_GPIO10: J11.15
PR1_PRU0_GPIO11: J11.16
PR1_PRU0_GPIO12: J11.17
PR1_PRU0_GPIO13: J11.18
PR1_PRU0_GPIO14: J11.19
PR1_PRU0_GPIO15: J11.20
PR1_PRU0_GPIO16: J11.21
PR1_PRU0_GPIO17: J11.22
PR1_PRU0_GPIO18: J11.23
PR1_PRU0_GPIO19: J11.24
PR1_PRU0_GPIO20: J11.25
PR1_PRU1_GPIO0: J11.29
PR1_PRU1_GPIO1: J11.30
PR1_PRU1_GPIO2: J11.31
PR1_PRU1_GPIO3: U27.2(D1)
PR1_PRU1_GPIO4: J11.33
PR1_PRU1_GPIO5: J11.34
PR1_PRU1_GPIO6: J11.35
PR1_PRU1_GPIO7: J11.36
PR1_PRU1_GPIO8: J11.37
PR1_PRU1_GPIO9: J11.38
PR1_PRU1_GPIO10: J11.39
PR1_PRU1_GPIO11: J11.40
PR1_PRU1_GPIO12: J11.41
PR1_PRU1_GPIO13: J11.42
PR1_PRU1_GPIO14: U28.2(D1)
PR1_PRU1_GPIO15: U27.5(D2)
PR1_PRU1_GPIO16: U27.7(D3)
PR1_PRU1_GPIO17: U28.5(D2)
PR1_PRU1_GPIO18: U28.7(D3)
PR1_PRU1_GPIO19: U28.10(D4)
SEL_HPI_FSI: R118.2 U26.15(SEL) U27.15(SEL) ; port HPI.SEL_HPI_FSI
SEL_HPI_SPI: R119.2 U28.15(SEL) ; port HPI.SEL_HPI_SPI
SEL_MMC: J18.2 R180.2 U49.15(SEL) U52.15(SEL)
SOP_DRIVER_OEN_HPI: U26.13(~{EN}) U27.13(~{EN}) U54.4(Y)
SPI2_CLK: J7.3 U28.4(S2B)
SPI2_CS0: J7.1 R220.1 U28.11(S4B)
SPI2_D0: J7.5 U28.8(S3B)
SPI2_D1: J7.6 U28.1(S1B)
SYNC_OUT1_3V3: J8.2 J11.52 U55.4(B)
NetC179_2: C179.2 C182.1 J6.4(VDD) L16.1
NetC181_2: C181.2 L16.2 R222.2 U50.6(VOUT)
NetJ11_50: J11.50 J12.2
NetR222_1: R222.1 U50.5(QOD)

Not connected (* = marked no-connect by the designer): J8 6*; J10 10* 11* 12*; J11 1* 57*; U19 4(NC)* 9(NC)*; U26 11(S4B) 12(S4A); U27 11(S4B) 12(S4A); U50 4(CT)*; U52 8(S3B) 9(S3A) 11(S4B) 12(S4A); U54 1(NC)*

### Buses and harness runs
bus HPI_IRQ[3..0]
bus MMC0_D[3..0]
bus PR0_IEP0_EDC_LATCH_IN[1..0]
bus PR0_IEP0_EDC_SYNC_OUT[1..0]
bus PR1_PRU0_GPIO[20..0]
bus PR1_PRU1_GPIO[19..0]

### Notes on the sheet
- (near U49) SDIO mux
- (near J7) SPI
- SYNC/LATCH
- (near J9) FSI
- SDIO
- (near J18) PCB label: SDIO mux
- Length match: PRU GPIO, MMC
- (near U26) FSI/ICSS1 MUX
- Level shifter SYNC1
- (near J6) SD card
- (near J11) Host Port Interface
- (near U54) PORZ SOP Buffer
- Text
- PCB label: 3.3V and 1.8V at pin 1 and 3
- SPI/ICSS1 MUX
- Interfaces on SAMTEC connector:
  ICSS MII, ICSS GPIO, FSI, SPI

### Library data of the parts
C117-C119 C196 C197 C211 C218 C219 = CMP-0006228-2: CAP, CERM, 0.1 uF, 16 V, +/- 10%, X7R, 0402; Manufacturer: Wurth Elektronik; TaMin_C: -55°C; Polarized: N; SizeAreaWB_mm2: 3; Value1: Unknown; U/M: EA; Value: 0.1uF; TaMax_C: 125°C; SizeZ_mm: 0.6; SizeX_mm: 1; SizeY_mm: 0.5; Cap_Case: 0402; Cap_F: 100nF; AEC Category: Q200
C179 = CMP-0006221-2: CAP, CERM, 0.1 uF, 10 V, +/- 20%, X5R, 0402; Manufacturer: Wurth Elektronik; TaMin_C: -55°C; Polarized: N; SizeAreaWB_mm2: 3; Value1: Unknown; U/M: EA; Value: 0.1uF; TaMax_C: 85°C; SizeZ_mm: 0.6; SizeX_mm: 1; SizeY_mm: 0.5; Cap_Case: 0402; Cap_F: 100nF; AEC Category: Q200
C180 C182 = CMP-0120207-1: 10 µF ±20% 10V Ceramic Capacitor X5R 0402 (1005 Metric); Manufacturer: Murata; AEC Qualified: No; Cap_F: 10µF; SizeZ_mm: 0.7mm; TempCo: 15%; Value: 10µF
C181 = CMP-0097305-1: 4.7 µF ±20% 10V Ceramic Capacitor X5R 0603 (1608 Metric); Manufacturer: Wurth Electronics; Cap_F: 4.7µF; Value: 4.7µF; AEC Qualified: No; SizeZ_mm: 0.87mm; TempCo: 15%
C193 = CMP-0096737-1: 100 nF ±10% 50V Ceramic Capacitor X7R 0402 (1005 Metric); Manufacturer: Wurth; SizeZ_mm: 0.7mm; TempCo: 15%; AEC Qualified: No; Value: 100nF
J6 = CMP-0078832-1: MicroSD Card Connector, R/A, Gold, SMT; Manufacturer: Wurth Elektronik; Pitch_mm: 1.1; Gender: Female; Cert_UL: Y; Voltage_V: 100V; Current_A: 5dA; Row_Count: 1
J7 J8 = CMP-0054802-2: Header, 2.54mm, 3x2, Gold, TH; Manufacturer: Wurth Elektronik; Green_Lifecycle: Active; Shrouded: N; Gender: Male; Green_REACh: Passed; Row_Count: 2; RowSpacing_mm: 2.54
J9 = CMP-0054806-3: Header, 2.54 mm, 5x2, Gold, TH; Manufacturer: Wurth Elektronik; Green_Lifecycle: Active; Green_REACh: Passed; Cert_UL: Y; Current_A: 3A; Gender: Male; Pitch_mm: 2.54; Row_Count: 2; Shrouded: N; Voltage_V: 250V
J10 = CMP-0092423-1: THT Vertical Pin Header WR-PHD, Pitch 2.54 mm, Dual Row, 12 pins; Manufacturer: Wurth Electronics; Is Female: no; DUT-Pitch_mm: 2.54mm; Row_Count: 2; Current_A: 3A; Voltage_V: 250V; Conn Gender: Male; Conn Orientation: Straight; SizeZ_mm: 8.89mm; ContactFinish: Gold
J11 = CMP-0075524-1: Receptacle, 0.5 mm, 30x2, Gold, TH; Manufacturer: Samtec; Pitch_mm: 0.5; Gender: Female; Green_REACh: Passed; CT: False; Shrouded: N; RowSpacing_mm: 5.73; Green_Lifecycle: Active; Row_Count: 2
J12 = CMP-0054796-4: Header, 2.54 mm, 3x1, Gold, TH; Manufacturer: Wurth Elektronik; Green_REACh: Passed; CT: FALSE; CNHeader: TRUE; Green_Lifecycle: Active
J18 = CMP-0054794-2: Header, 2.54 mm, 2x1, Gold, TH; Manufacturer: Wurth Elektronik; Shrouded: N; Gender: Male; Green_REACh: Passed; Pitch_mm: 2.54; Green_Lifecycle: Active; Row_Count: 1; Cert_UL: Y
L16 = CMP-0003200-2: Ferrite Bead, 1000 ohm @ 100 MHz, 0.2 A, 0603; Manufacturer: Wurth Elektronik; Ztyp@1GHz_Ohm: 265.464; ZTyp@100MHz_Ohm: 1k; SizeAreaWB_mm2: 4.68; DCR_ohm: 6d; Value1: 0.6 ohm; Imax_A: 2dA; SizeZ_mm: 1; SizeX_mm: 1.6; SizeY_mm: 0.8; Value2: 0.2A; SizeArea_mm2: 1.28
R118 R119 R175-R180 R220 R221 = CMP-0025958-3: RES, 10.0 k, 1%, 0.063 W, AEC-Q200 Grade 0, 0402; Manufacturer: Vishay-Dale; Power_W: 63mW; TempCo: 100 ppm/C; Value_Code: 10k0; Value: 10.0k; EIA_Code: E96; Res_ohm: 10k; SizeX_mm: 1; SizeY_mm: 0.5; SizeZ_mm: 0.6; Value2: 0.063W; AEC Qualified: Y; VDC_V: 50V; AEC Category: Q200; AEC Grade: 0
R222 = CMP-0093210-1: Jumper 0.063W, 1/16W Chip Resistor 0402 (1005 Metric) - Thick Film; Manufacturer: Vishay; AEC Qualified: No; VDC_V: 50V; Power_W: 63mW; SizeZ_mm: 0.35mm
SH-J2 = CMP-0003761-2: Shunt, 2.54mm, Gold, Black; Manufacturer: Wurth Elektronik
U19 = CMP-0043123-1: Low-Capacitance + / - 15 kV ESD Protection Array for High-Speed Data Interfaces, 6 Channels, -40 to +85 degC, 10-pin UQFN (RSE), Green (RoHS & no Sb/Br); Manufacturer: Texas Instruments; Serial ATA / eSATA: TRUE; IO Leakage Current(nA): 1; IO Capacitance(Typ)(pF): 1.5; IEC 61000-4-2 Contact(+/- kV): 8; Breakdown Voltage(Min)(V): 11; IEC 61000-4-2 Air-Gap(+/- kV): 15; SubFamily: ESD Solution
U26-U28 U49 U52 = CMP-0086167-3: Low-capacitance, 2:1 (SPDT) 4-channel, powered-off protection switch with 1.8 V logic, RSV0016A (UQFN-16); Manufacturer: Texas Instruments; SizeArea_mm2: 4.68; CompType: IC; AEC Qualified: N; SizeAreaWB_mm2: 10.08; SizeX_mm: 1.8; SizeZ_mm: 0.55; AEC Category: Q200; SizeY_mm: 2.6; Rating: Catalog
U50 = CMP-0122847-1: 5.5-V, 2-A, 52-mΩ load switch with adj. rise time and adj. output discharge; Manufacturer: Texas Instruments; SizeZ_mm: 1.45mm; AEC Qualified: No; Fall Time: 2us; Max Supply Voltage: 5.5V; Nominal Supply Current: 8.3-10.2uA; Number Of Drivers: 1; Rise Time: 2540us; Standoff Height: 0mm; TaMax_C: +105°C; TaMin_C: -40°C; TJmax_C: +125°C; Turn On Delay Time: 1950us
U54 = CMP-0051682-2: Single Inverter Gate, DRL0005A, LARGE T&R; Manufacturer: Texas Instruments; VCC(Min)(V): 2; F @ Nom Voltage(Max)(Mhz): 75; VCC(Max)(V): 5.5; Output Type: CMOS; Voltage(Nom)(V): 3.3,5; Schmitt Trigger: No; Logic: Inverting; Technology Family: AHC; tpd @ Nom Voltage(Max)(ns): 10.6,7.5; Rating: Catalog; Sub-Family: Inverting Buffer/Driver; Output Drive (IOL/IOH)(Max)(mA): 50/-50; ICC @ Nom Voltage(Max)(mA): 0.01; Bits(#): 1; AEC Category: Q200; AEC Qualified: N; CompType: IC; SizeArea_mm2: 2.56; SizeX_mm: 1.6; SizeZ_mm: 0.6
U55 = CMP-0081179-1: Single-Bit Dual-Supply Bus Transceiver, DRL0006A (SOT-OTHER-6); Alternate Manufacturer: Texas Instruments; SizeAreaWB_mm2: 6.76; SizeZ_mm: 0.6; SizeX_mm: 1.6; SizeArea_mm2: 2.56; CompType: IC; AEC Qualified: N; AEC Category: Q200

## Sheet TIDA-010973_SOM_BlockDiagram.SchDoc
size 431 x 279 mm; Date: Not shown in title block; ApprovedBy: Not shown in title block; CheckedBy: Not shown in title block; Author: Not shown in title block; CompanyName: Not shown in title block; Engineer: Not shown in title block; Organization: Not shown in title block; Address1: Not shown in title block; Address2: Not shown in title block; Address3: Not shown in title block; Address4: Not shown in title block; DocumentNumber: 2; Revision: Use project parameter SCH_Rev; SheetNumber: 2; SheetTotal: 15; PageSetup: Record=PageOptions¦CenterHorizontal=True¦CenterVertical=True¦PrintScale=1.00¦XCorrection=1.00¦YCorrection=1.00¦PrintKind=0¦BorderSize=5000000¦LeftOffset=0¦BottomOffset=0¦Orientation=2¦PaperLength=1000¦PaperWidth=1000¦Scale=100¦PaperSource=15¦PrintQuality=600¦MediaType=1¦DitherType=10¦PaperKind=Letter¦PrintScaleMode=1
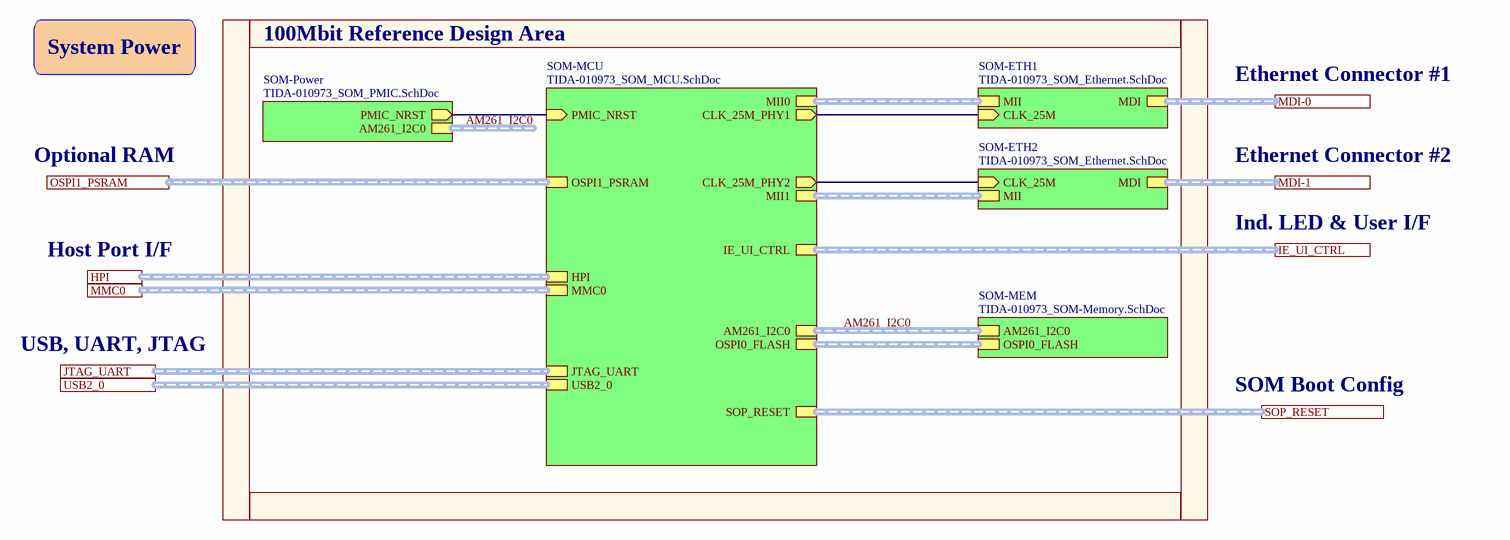
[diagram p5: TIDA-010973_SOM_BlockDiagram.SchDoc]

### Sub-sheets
SOM-ETH1 = TIDA-010973_SOM_Ethernet.SchDoc: MII (harness MII), MDI (harness MDI), CLK_25M (in)
SOM-ETH2 = TIDA-010973_SOM_Ethernet.SchDoc: MII (harness MII), MDI (harness MDI), CLK_25M (in)
SOM-MCU = TIDA-010973_SOM_MCU.SchDoc: MII0 (harness MII), MII1 (harness MII), OSPI0_FLASH (harness OSPI), OSPI1_PSRAM (harness OSPI), AM261_I2C0 (harness I2C), IE_UI_CTRL (harness IE_UI_CTRL), SOP_RESET (harness SOP_RESET), MMC0 (harness MMC), HPI (harness HPI), JTAG_UART (harness JTAG_UART), PMIC_NRST (in), USB2_0 (harness USB2_0), CLK_25M_PHY2 (out), CLK_25M_PHY1 (out)
SOM-MEM = TIDA-010973_SOM-Memory.SchDoc: OSPI0_FLASH (harness OSPI), AM261_I2C0 (harness I2C)
SOM-Power = TIDA-010973_SOM_PMIC.SchDoc: PMIC_NRST (out), AM261_I2C0 (harness I2C)

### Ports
HPI (harness HPI), IE_UI_CTRL (harness IE_UI_CTRL), JTAG_UART (harness JTAG_UART), MDI-0 (harness MDI), MDI-1 (harness MDI), MMC0 (harness MMC), OSPI1_PSRAM (harness OSPI), SOP_RESET (harness SOP_RESET), USB2_0 (harness USB2_0)

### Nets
CLK_25M: sheet SOM-ETH1/CLK_25M, sheet SOM-MCU/CLK_25M_PHY1
CLK_25M: sheet SOM-MCU/CLK_25M_PHY2, sheet SOM-ETH2/CLK_25M  [a separate net that carries the same name]
PMIC_NRST: sheet SOM-Power/PMIC_NRST, sheet SOM-MCU/PMIC_NRST

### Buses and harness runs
harness AM261_I2C0 = sheet SOM-MCU/AM261_I2C0 = sheet SOM-MEM/AM261_I2C0
harness AM261_I2C0 = sheet SOM-Power/AM261_I2C0
harness port HPI = sheet SOM-MCU/HPI
harness port IE_UI_CTRL = sheet SOM-MCU/IE_UI_CTRL
harness port JTAG_UART = sheet SOM-MCU/JTAG_UART
harness port MDI-0 = sheet SOM-ETH1/MDI
harness port MDI-1 = sheet SOM-ETH2/MDI
harness port MMC0 = sheet SOM-MCU/MMC0
harness port OSPI1_PSRAM = sheet SOM-MCU/OSPI1_PSRAM
harness port SOP_RESET = sheet SOM-MCU/SOP_RESET
harness port USB2_0 = sheet SOM-MCU/USB2_0
harness sheet SOM-ETH1/MII = sheet SOM-MCU/MII0
harness sheet SOM-ETH2/MII = sheet SOM-MCU/MII1
harness sheet SOM-MCU/OSPI0_FLASH = sheet SOM-MEM/OSPI0_FLASH

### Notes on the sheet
- System Power
- 100Mbit Reference Design Area
- Ethernet Connector #1
- Optional RAM
- Ethernet Connector #2
- Host Port I/F
- Ind. LED & User I/F
- USB, UART, JTAG
- SOM Boot Config

## Sheet TIDA-010973_SOM-Memory.SchDoc
size 431 x 279 mm; Date: Not shown in title block; ApprovedBy: Not shown in title block; CheckedBy: Not shown in title block; Author: Not shown in title block; CompanyName: Not shown in title block; Engineer: Not shown in title block; Organization: Not shown in title block; Address1: Not shown in title block; Address2: Not shown in title block; Address3: Not shown in title block; Address4: Not shown in title block; DocumentNumber: 2; Revision: Use project parameter SCH_Rev; SheetNumber: 6; SheetTotal: 15; PageSetup: Record=PageOptions¦CenterHorizontal=True¦CenterVertical=True¦PrintScale=1.00¦XCorrection=1.00¦YCorrection=1.00¦PrintKind=0¦BorderSize=5000000¦LeftOffset=0¦BottomOffset=0¦Orientation=2¦PaperLength=1000¦PaperWidth=1000¦Scale=100¦PaperSource=15¦PrintQuality=600¦MediaType=1¦DitherType=10¦PaperKind=Letter¦PrintScaleMode=1
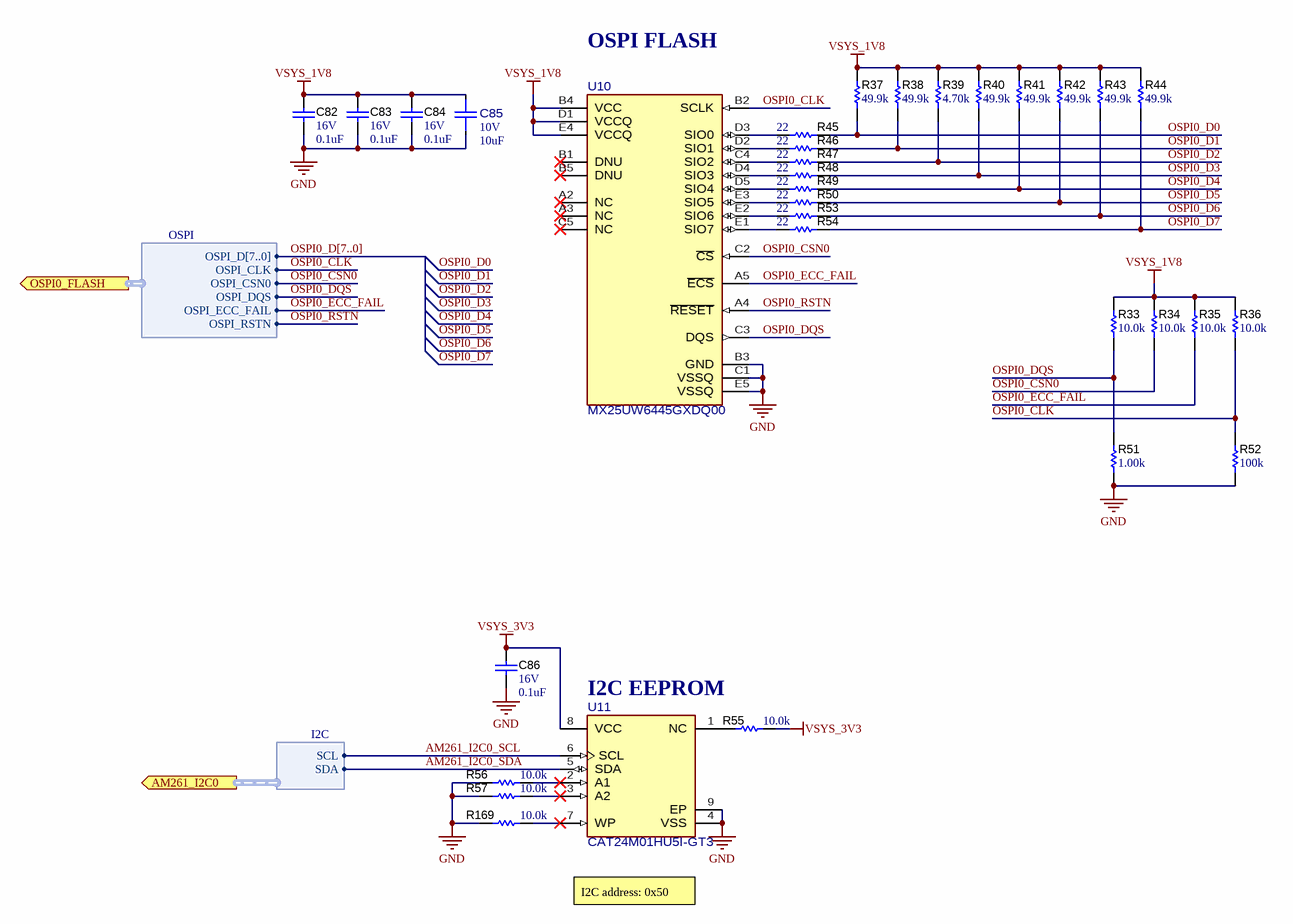
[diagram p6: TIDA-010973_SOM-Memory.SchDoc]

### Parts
C82  VDC_V: 16V  ValueDisplayed: 0.1uF  [0402L]  (hidden comment: 885012205037)
C83  VDC_V: 16V  ValueDisplayed: 0.1uF  [0402L]  (hidden comment: 885012205037)
C84  VDC_V: 16V  ValueDisplayed: 0.1uF  [0402L]  (hidden comment: 885012205037)
C85  ValueDisplayed: 10uF  VDC_V: 10V  [FP-GRM155R61A106ME18D_0402-MFG]  (hidden comment: GRM155R61A106ME18D)
C86  VDC_V: 16V  ValueDisplayed: 0.1uF  [0402L]  (hidden comment: 885012205037)
R33  ValueDisplayed: 10.0k  [0402L]  (hidden comment: CRCW040210K0FKED)
R34  ValueDisplayed: 10.0k  [0402L]  (hidden comment: CRCW040210K0FKED)
R35  ValueDisplayed: 10.0k  [0402L]  (hidden comment: CRCW040210K0FKED)
R36  ValueDisplayed: 10.0k  [0402L]  (hidden comment: CRCW040210K0FKED)
R37  ValueDisplayed: 49.9k  [0201L]  (hidden comment: RC0201FR-0749K9L)
R38  ValueDisplayed: 49.9k  [0201L]  (hidden comment: RC0201FR-0749K9L)
R39  ValueDisplayed: 4.70k  [0201_033L]  (hidden comment: CRCW02014K70FKED)
R40  ValueDisplayed: 49.9k  [0201L]  (hidden comment: RC0201FR-0749K9L)
R41  ValueDisplayed: 49.9k  [0201L]  (hidden comment: RC0201FR-0749K9L)
R42  ValueDisplayed: 49.9k  [0201L]  (hidden comment: RC0201FR-0749K9L)
R43  ValueDisplayed: 49.9k  [0201L]  (hidden comment: RC0201FR-0749K9L)
R44  ValueDisplayed: 49.9k  [0201L]  (hidden comment: RC0201FR-0749K9L)
R45  ValueDisplayed: 22  [0201L]  (hidden comment: RC0201JR-0722RL)
R46  ValueDisplayed: 22  [0201L]  (hidden comment: RC0201JR-0722RL)
R47  ValueDisplayed: 22  [0201L]  (hidden comment: RC0201JR-0722RL)
R48  ValueDisplayed: 22  [0201L]  (hidden comment: RC0201JR-0722RL)
R49  ValueDisplayed: 22  [0201L]  (hidden comment: RC0201JR-0722RL)
R50  ValueDisplayed: 22  [0201L]  (hidden comment: RC0201JR-0722RL)
R51  ValueDisplayed: 1.00k  [0402L]  (hidden comment: CRCW04021K00FKED)
R52  ValueDisplayed: 100k  [0402L]  (hidden comment: CRCW0402100KFKED)
R53  ValueDisplayed: 22  [0201L]  (hidden comment: RC0201JR-0722RL)
R54  ValueDisplayed: 22  [0201L]  (hidden comment: RC0201JR-0722RL)
R55  ValueDisplayed: 10.0k  [0402L]  (hidden comment: CRCW040210K0FKED)
R56  ValueDisplayed: 10.0k  [0402L]  (hidden comment: CRCW040210K0FKED)
R57  ValueDisplayed: 10.0k  [0402L]  (hidden comment: CRCW040210K0FKED)
R169  ValueDisplayed: 10.0k  [0402L]  (hidden comment: CRCW040210K0FKED)
U10  MX25UW6445GXDQ00  [FP-MX25UW6445GXDQ00_BGA24-IPC_C]
U11  CAT24M01HU5I-GT3  [FP-CAT24M01HU5I-GT3_UDFN8-IPC_A]

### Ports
AM261_I2C0 (out, harness I2C), OSPI0_FLASH (out, harness OSPI)

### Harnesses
OSPI: OSPI_CLK, OSPI_CSN0, OSPI_DQS, OSPI_ECC_FAIL, OSPI_D[7..0], OSPI_RSTN
I2C: SCL, SDA

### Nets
GND: C82.2 C83.2 C84.2 C85.1 C86.2 R51.1 R52.1 R56.1 R57.1 R169.1 U10.B3(GND) U10.C1(VSSQ) U10.E5(VSSQ) U11.4(VSS) U11.9(EP)
VSYS_1V8: C82.1 C83.1 C84.1 C85.2 R33.2 R34.2 R35.2 R36.2 R37.2 R38.2 R39.2 R40.2 R41.2 R42.2 R43.2 R44.2 U10.B4(VCC) U10.D1(VCCQ) U10.E4(VCCQ)
VSYS_3V3: C86.1 R55.2 U11.8(VCC)
AM261_I2C0_SCL: U11.6(SCL) ; port AM261_I2C0.SCL  [project net AM261_I2C0.SCL]
AM261_I2C0_SDA: U11.5(SDA) ; port AM261_I2C0.SDA  [project net AM261_I2C0.SDA]
OSPI0_CLK: R36.1 R52.2 U10.B2(SCLK) ; port OSPI0_FLASH.OSPI_CLK
OSPI0_CSN0: R34.1 U10.C2(~{CS}) ; port OSPI0_FLASH.OSPI_CSN0
OSPI0_D0: R37.1 R45.2
OSPI0_D1: R38.1 R46.2
OSPI0_D2: R39.1 R47.2
OSPI0_D3: R40.1 R48.2
OSPI0_D4: R41.1 R49.2
OSPI0_D5: R42.1 R50.2
OSPI0_D6: R43.1 R53.2
OSPI0_D7: R44.1 R54.2
OSPI0_DQS: R33.1 R51.2 U10.C3(DQS) ; port OSPI0_FLASH.OSPI_DQS
OSPI0_ECC_FAIL: R35.1 U10.A5(~{ECS}) ; port OSPI0_FLASH.OSPI_ECC_FAIL
OSPI0_RSTN: U10.A4(~{RESET}) ; port OSPI0_FLASH.OSPI_RSTN
NetR45_1: R45.1 U10.D3(SIO0)
NetR46_1: R46.1 U10.D2(SIO1)
NetR47_1: R47.1 U10.C4(SIO2)
NetR48_1: R48.1 U10.D4(SIO3)
NetR49_1: R49.1 U10.D5(SIO4)
NetR50_1: R50.1 U10.E3(SIO5)
NetR53_1: R53.1 U10.E2(SIO6)
NetR54_1: R54.1 U10.E1(SIO7)
NetR55_1: R55.1 U11.1(NC)
NetR56_2: R56.2 U11.2(A1)
NetR57_2: R57.2 U11.3(A2)
NetR169_2: R169.2 U11.7(WP)

Not connected (* = marked no-connect by the designer): U10 A2(NC)* A3(NC)* B1(DNU)* B5(DNU)* C5(NC)*

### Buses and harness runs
bus OSPI0_D[7..0]

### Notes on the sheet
- OSPI FLASH
- (near U11) I2C EEPROM
- I2C address: 0x50

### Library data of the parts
C82-C84 C86 = CMP-0006228-2: as C117 on sheet TIDA-010973_HostPortInterface
C85 = CMP-0120207-1: as C180 on sheet TIDA-010973_HostPortInterface
R33-R36 R55-R57 R169 = CMP-0025958-3: as R118 on sheet TIDA-010973_HostPortInterface
R37 R38 R40-R44 = CMP-0027732-1: RES, 49.9 k, 1%, 0.05 W, 0201; Manufacturer: Yageo America; Power_W: 50mW; TempCo: 200 ppm/C; Value_Code: 49k9; U/M: EA; Value: 49.9k; EIA_Code: E96; SizeX_mm: 0.6; SizeY_mm: 0.3; SizeZ_mm: 0.26; Value2: 0.05W; SizeArea_mm2: 0.18; AEC Qualified: N; VDC_V: 25V; AEC Category: Q200
R39 = CMP-0027280-3: RES, 4.70 k, 1%, 0.05 W, 0201; Manufacturer: Vishay-Dale; Power_W: 50mW; TempCo: 100 ppm/C; Value_Code: 4k70; Value: 4.70k; Res_ohm: 4.7k; SizeX_mm: 0.6; SizeY_mm: 0.3; SizeZ_mm: 0.33; Value2: 0.05W; SizeArea_mm2: 0.18; AEC Qualified: N; VDC_V: 30V; AEC Category: Q200
R45-R50 R53 R54 = CMP-0027074-3: RES, 22, 5%, 0.05 W, 0201; Manufacturer: Yageo America; Power_W: 50mW; TempCo: 200 ppm/C; Value_Code: 22R0; U/M: EA; Value: 22; EIA_Code: E24; SizeX_mm: 0.6; SizeY_mm: 0.3; SizeZ_mm: 0.26; Value2: 0.05W; SizeArea_mm2: 0.18; AEC Qualified: N; VDC_V: 25V; AEC Category: Q200
R51 = CMP-0026071-3: RES, 1.00 k, 1%, 0.063 W, AEC-Q200 Grade 0, 0402; Manufacturer: Vishay-Dale; Power_W: 63mW; TempCo: 100 ppm/C; Value_Code: 1k00; Value: 1.00k; EIA_Code: E96; Res_ohm: 1k; SizeX_mm: 1; SizeY_mm: 0.5; SizeZ_mm: 0.6; Value2: 0.063W; AEC Qualified: Y; VDC_V: 50V; AEC Category: Q200; AEC Grade: 0
R52 = CMP-0025950-3: RES, 100 k, 1%, 0.063 W, AEC-Q200 Grade 0, 0402; Manufacturer: Vishay-Dale; Power_W: 63mW; TempCo: 100 ppm/C; Value: 100k; EIA_Code: E96; SizeX_mm: 1; SizeY_mm: 0.5; SizeZ_mm: 0.6; Value2: 0.063W; AEC Qualified: Y; VDC_V: 50V; AEC Category: Q200; AEC Grade: 0
U10 = CMP-0122153-1: 1.8V 64M-BIT [x 1/x 8] Read-While-Write octaflash Memory; Manufacturer: Macronix; SizeZ_mm: 1.2mm; Access Time: 5ns; AEC Grade: Grade 1; AEC Qualified: Yes; Frequency_Fixed: 200MHz; Interface: SPI; Max Supply Voltage: 2V; Memory Size: 64Mbits; Memory Type: FLASH,NOR; Min Supply Voltage: 1.7V; Nominal Supply Current: 18-140mA; Standoff Height: 0.25mm; TaMax_C: +125°C; TaMin_C: -40°C
U11 = CMP-0126419-1: EEPROM Serial-I2C 1M-bit 128K x 8 2.5V/3.3V/5V 8-Pin UDFN EP T/R; Manufacturer: onsemi; SizeZ_mm: 0.55mm; Access Time: 3.5us; AEC Qualified: No; Frequency_Fixed: 1MHz; Interface: I2C; Max Supply Voltage: 5.5V; Memory Size: 1Mbits; Min Supply Voltage: 1.8V; Nominal Supply Current: 1-5mA; Standoff Height: 0mm; TaMax_C: +85°C; TaMin_C: -40°C; TJmax_C: +150°C

## Sheet TIDA-010973_SOM_Ethernet.SchDoc
size 431 x 279 mm; Date: Not shown in title block; ApprovedBy: Not shown in title block; CheckedBy: Not shown in title block; Author: Not shown in title block; CompanyName: Not shown in title block; Engineer: Not shown in title block; Organization: Not shown in title block; Address1: Not shown in title block; Address2: Not shown in title block; Address3: Not shown in title block; Address4: Not shown in title block; DocumentNumber: 2; Revision: Use project parameter SCH_Rev; SheetNumber: 5; SheetTotal: 15; PageSetup: Record=PageOptions¦CenterHorizontal=True¦CenterVertical=True¦PrintScale=1.00¦XCorrection=1.00¦YCorrection=1.00¦PrintKind=0¦BorderSize=5000000¦LeftOffset=0¦BottomOffset=0¦Orientation=2¦PaperLength=1000¦PaperWidth=1000¦Scale=100¦PaperSource=15¦PrintQuality=600¦MediaType=1¦DitherType=10¦PaperKind=Letter¦PrintScaleMode=1
Used 2 times, as channels SOM/SOM-ETH1, SOM/SOM-ETH2. Parts and nets are listed once, with the designators drawn on the sheet.
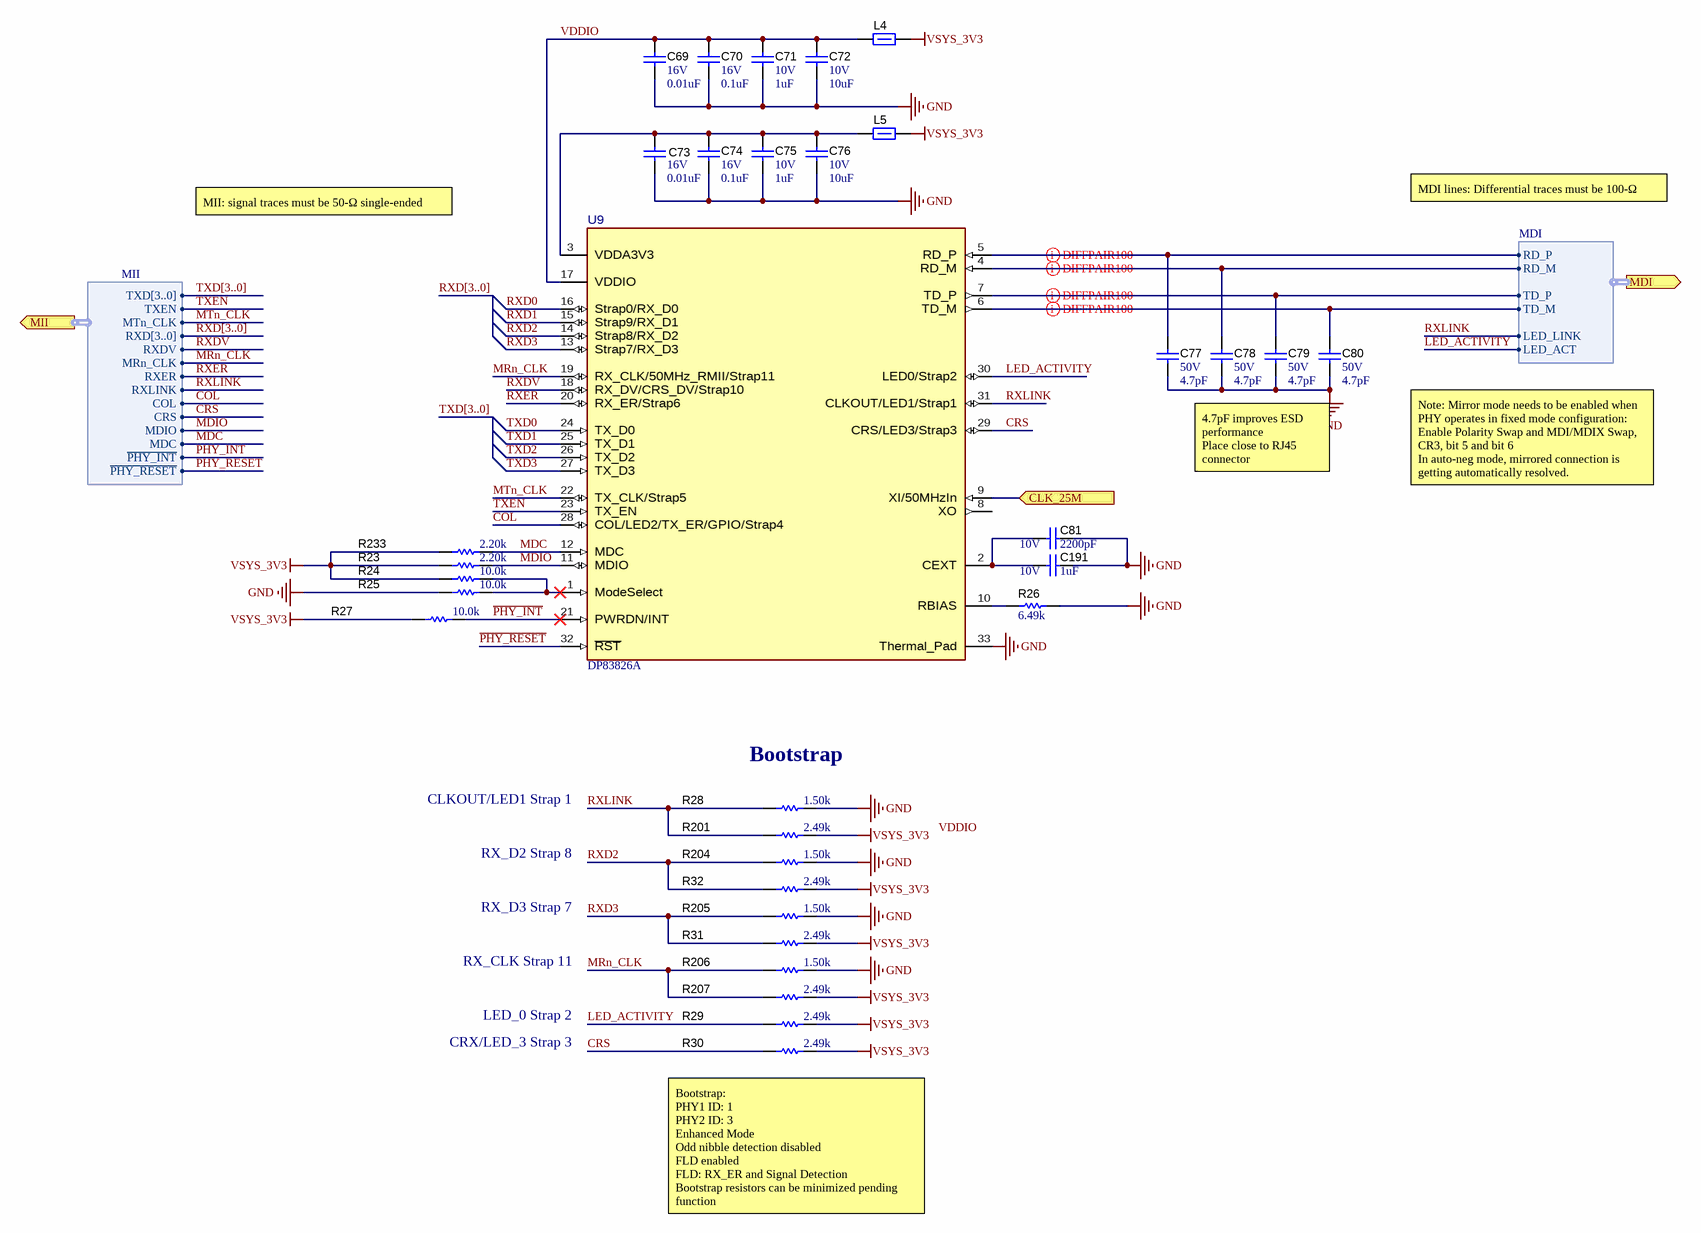
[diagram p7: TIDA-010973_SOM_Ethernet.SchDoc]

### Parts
C69  VDC_V: 16V  ValueDisplayed: 0.01uF  [0402L]  (hidden comment: 885012205031)
C70  VDC_V: 16V  ValueDisplayed: 0.1uF  [0402L]  (hidden comment: 885012205037)
C71  VDC_V: 10V  ValueDisplayed: 1uF  [0402L]  (hidden comment: 885012105012)
C72  VDC_V: 10V  ValueDisplayed: 10uF  [0402L]  (hidden comment: GRM155R61A106ME11D)
C73  VDC_V: 16V  ValueDisplayed: 0.01uF  [0402L]  (hidden comment: 885012205031)
C74  VDC_V: 16V  ValueDisplayed: 0.1uF  [0402L]  (hidden comment: 885012205037)
C75  VDC_V: 10V  ValueDisplayed: 1uF  [0402L]  (hidden comment: 885012105012)
C76  VDC_V: 10V  ValueDisplayed: 10uF  [0402L]  (hidden comment: GRM155R61A106ME11D)
C77  VDC_V: 50V  ValueDisplayed: 4.7pF  [0402L]  (hidden comment: GRM1555C1H4R7CA01D)
C78  VDC_V: 50V  ValueDisplayed: 4.7pF  [0402L]  (hidden comment: GRM1555C1H4R7CA01D)
C79  VDC_V: 50V  ValueDisplayed: 4.7pF  [0402L]  (hidden comment: GRM1555C1H4R7CA01D)
C80  VDC_V: 50V  ValueDisplayed: 4.7pF  [0402L]  (hidden comment: GRM1555C1H4R7CA01D)
C81  VDC_V: 10V  ValueDisplayed: 2200pF  [0402L]  (hidden comment: 885012205008)
C191  VDC_V: 10V  ValueDisplayed: 1uF  [0402L]  (hidden comment: 885012105012)
L4  742792604  [0603L]  (value not drawn)
L5  742792604  [0603L]  (value not drawn)
R23  ValueDisplayed: 2.20k  [0402L]  (hidden comment: CRCW04022K20FKED)
R24  ValueDisplayed: 10.0k  [0402L]  (hidden comment: CRCW040210K0FKED)
R25  ValueDisplayed: 10.0k  [0402L]  (hidden comment: CRCW040210K0FKED)
R26  ValueDisplayed: 6.49k  [0402L]  (hidden comment: CRCW04026K49FKED)
R27  ValueDisplayed: 10.0k  [0402L]  (hidden comment: CRCW040210K0FKED)
R28  ValueDisplayed: 1.50k  [0402L]  (hidden comment: CRCW04021K50FKED)
R29  ValueDisplayed: 2.49k  [0402L]  (hidden comment: CRCW04022K49FKED)
R30  ValueDisplayed: 2.49k  [0402L]  (hidden comment: CRCW04022K49FKED)
R31  ValueDisplayed: 2.49k  [0402L]  (hidden comment: CRCW04022K49FKED)
R32  ValueDisplayed: 2.49k  [0402L]  (hidden comment: CRCW04022K49FKED)
R201  ValueDisplayed: 2.49k  [0402L]  (hidden comment: CRCW04022K49FKED)
R204  ValueDisplayed: 1.50k  [0402L]  (hidden comment: CRCW04021K50FKED)
R205  ValueDisplayed: 1.50k  [0402L]  (hidden comment: CRCW04021K50FKED)
R206  ValueDisplayed: 1.50k  [0402L]  (hidden comment: CRCW04021K50FKED)
R207  ValueDisplayed: 2.49k  [0402L]  (hidden comment: CRCW04022K49FKED)
R233  ValueDisplayed: 2.20k  [0402L]  (hidden comment: CRCW04022K20FKED)
U9  DP83826A  [RHB0032M-MFG]

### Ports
CLK_25M (in), MDI (out, harness MDI), MII (out, harness MII)

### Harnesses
MII: TXEN, MTn_CLK, RXD[3..0], RXDV, RXLINK, MDIO, MDC, TXD[3..0], ~{PHY_INT}, ~{PHY_RESET}, COL, CRS, RXER, MRn_CLK
MDI: RD_M, TD_P, TD_M, LED_LINK, RD_P, LED_ACT

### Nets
GND: C69.2 C70.2 C71.2 C72.2 C73.2 C74.2 C75.2 C76.2 C77.2 C78.2 C79.2 C80.2 C81.1 C191.2 R25.1 R26.1 R28.2 R204.2 R205.2 R206.2 U9.33(Thermal_Pad)
VSYS_3V3: L4.2 L5.2 R23.1 R24.1 R27.1 R29.1 R30.1 R31.1 R32.1 R201.1 R207.1 R233.1
~{PHY_INT}: R27.2 U9.21(PWRDN/INT) ; port MII.~{PHY_INT}
~{PHY_RESET}: U9.32(~{RST}) ; port MII.~{PHY_RESET}
CLK_25M: U9.9(XI/50MHzIn) ; port CLK_25M
COL: U9.28(COL/LED2/TX_ER/GPIO/Strap4) ; port MII.COL
CRS: R30.2 U9.29(CRS/LED3/Strap3) ; port MII.CRS
LED_ACTIVITY: R29.2 U9.30(LED0/Strap2) ; port MDI.LED_ACT
MDC: R233.2 U9.12(MDC) ; port MII.MDC
MDIO: R23.2 U9.11(MDIO) ; port MII.MDIO
MRn_CLK: R206.1 R207.2 U9.19(RX_CLK/50MHz_RMII/Strap11) ; port MII.MRn_CLK
MTn_CLK: U9.22(TX_CLK/Strap5) ; port MII.MTn_CLK
RXD0: U9.16(Strap0/RX_D0)
RXD1: U9.15(Strap9/RX_D1)
RXD2: R32.2 R204.1 U9.14(Strap8/RX_D2)
RXD3: R31.2 R205.1 U9.13(Strap7/RX_D3)
RXDV: U9.18(RX_DV/CRS_DV/Strap10) ; port MII.RXDV
RXER: U9.20(RX_ER/Strap6) ; port MII.RXER
RXLINK: R28.1 R201.2 U9.31(CLKOUT/LED1/Strap1) ; port MII.RXLINK, port MDI.LED_LINK
TXD0: U9.24(TX_D0)
TXD1: U9.25(TX_D1)
TXD2: U9.26(TX_D2)
TXD3: U9.27(TX_D3)
TXEN: U9.23(TX_EN) ; port MII.TXEN
VDDIO: C69.1 C70.1 C71.1 C72.1 L4.1 U9.17(VDDIO)
NetC73_1: C73.1 C74.1 C75.1 C76.1 L5.1 U9.3(VDDA3V3)
NetC77_1: C77.1 U9.5(RD_P) ; port MDI.RD_P
NetC78_1: C78.1 U9.4(RD_M) ; port MDI.RD_M
NetC79_1: C79.1 U9.7(TD_P) ; port MDI.TD_P
NetC80_1: C80.1 U9.6(TD_M) ; port MDI.TD_M
NetC81_2: C81.2 C191.1 U9.2(CEXT)
NetR24_2: R24.2 R25.2 U9.1(ModeSelect)
NetR26_2: R26.2 U9.10(RBIAS)

Not connected (* = marked no-connect by the designer): U9 8(XO)

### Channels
SOM/SOM-ETH1: designators end in _SOM-ETH1; ports CLK_25M=CLK_25M
SOM/SOM-ETH2: designators end in _SOM-ETH2; ports CLK_25M=CLK_25M

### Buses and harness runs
bus RXD[3..0]
bus TXD[3..0]

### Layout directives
differential pair: ETH0_RD_N, ETH0_RD_P, ETH0_TD_N, ETH0_TD_P

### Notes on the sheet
- MDI lines: Differential traces must be 100-Ω
- MII: signal traces must be 50-Ω single-ended impedance
- 4.7pF improves ESD performance
  Place close to RJ45 connector
- Note: Mirror mode needs to be enabled when PHY operates in fixed mode configuration: Enable Polarity Swap and MDI/MDIX Swap, CR3, bit 5 and bit 6
  In auto-neg mode, mirrored connection is getting automatically resolved.
- CLKOUT/LED1 Strap 1
- (near R28) Bootstrap
- RX_D2 Strap 8
- RX_D3 Strap 7
- RX_CLK Strap 11
- LED_0 Strap 2
- CRX/LED_3 Strap 3
- (near R30) Bootstrap:
  PHY1 ID: 1
  PHY2 ID: 3
  Enhanced Mode
  Odd nibble detection disabled
  FLD enabled
  FLD: RX_ER and Signal Detection
  Bootstrap resistors can be minimized pending function
- Labels drawn without touching a wire or pin: VDDIO

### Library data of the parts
C69 C73 = CMP-0006227-2: CAP, CERM, 0.01 uF, 16 V, +/- 10%, X7R, 0402; Manufacturer: Wurth Elektronik; TaMin_C: -55°C; Polarized: N; SizeAreaWB_mm2: 3; Value1: Unknown; U/M: EA; Value: 0.01uF; TaMax_C: 125°C; SizeZ_mm: 0.6; SizeX_mm: 1; SizeY_mm: 0.5; Cap_Case: 0402; Cap_F: 10nF; AEC Category: Q200
C70 C74 = CMP-0006228-2: as C117 on sheet TIDA-010973_HostPortInterface
C71 C75 C191 = CMP-0064924-2: CAP, CERM, 1 uF, 10 V,+/- 20%, X5R, 0402; Manufacturer: Wurth Elektronik; TaMin_C: -55°C; Polarized: N; SizeAreaWB_mm2: 3; Value1: Unknown; U/M: EA; Value: 1uF; TaMax_C: 85°C; SizeZ_mm: 0.6; SizeX_mm: 1; SizeY_mm: 0.5; Cap_Case: 0402; Cap_F: 1µF; AEC Category: Q200
C72 C76 = CMP-0006564-3: CAP, CERM, 10 uF, 10 V, +/- 20%, X5R, 0402; Manufacturer: MuRata; TaMin_C: -55°C; Polarized: N; SizeAreaWB_mm2: 3; Value1: Unknown; U/M: EA; Value: 10uF; TaMax_C: 85°C; SizeZ_mm: 0.6; SizeX_mm: 1; SizeY_mm: 0.5; Cap_Case: 0402; Cap_F: 10µF; AEC Category: Q200
C77-C80 = CMP-0006472-2: CAP, CERM, 4.7 pF, 50 V, +/- 5%, C0G/NP0, 0402; Manufacturer: MuRata; TaMin_C: -55°C; Polarized: N; SizeAreaWB_mm2: 3; Value1: Unknown; U/M: EA; Value: 4.7pF; TaMax_C: 125°C; SizeZ_mm: 0.6; SizeX_mm: 1; SizeY_mm: 0.5; Cap_Case: 0402; AEC Category: Q200
C81 = CMP-0006224-2: CAP, CERM, 2200 pF, 10 V, +/- 10%, X7R, 0402; Manufacturer: Wurth Elektronik; TaMin_C: -55°C; Polarized: N; SizeAreaWB_mm2: 3; Value1: Unknown; U/M: EA; Value: 2200pF; TaMax_C: 125°C; SizeZ_mm: 0.6; SizeX_mm: 1; SizeY_mm: 0.5; Cap_Case: 0402; Cap_F: 2.2nF; AEC Category: Q200
L4 L5 = CMP-0003175-2: Ferrite Bead, 22 ohm @ 100 MHz, 1 A, 0603; Manufacturer: Wurth Elektronik; Ztyp@1GHz_Ohm: 35.365; ZTyp@100MHz_Ohm: 22; SizeAreaWB_mm2: 4.68; DCR_ohm: 0.05; Value1: 0.05 ohm; Value: 22 ohm; Imax_A: 1A; SizeZ_mm: 1; SizeX_mm: 1.6; SizeY_mm: 0.8; SizeArea_mm2: 1.28
R23 R233 = CMP-0026231-2: RES, 2.20 k, 1%, 0.063 W, AEC-Q200 Grade 0, 0402; Manufacturer: Vishay-Dale; Power_W: 63mW; TempCo: 100 ppm/C; Value_Code: 2k20; Value: 2.20k; Res_ohm: 2.2k; SizeX_mm: 1; SizeY_mm: 0.5; SizeZ_mm: 0.6; Value2: 0.063W; AEC Qualified: Y; AEC Category: Q200; AEC Grade: 0
R24 R25 R27 = CMP-0025958-3: as R118 on sheet TIDA-010973_HostPortInterface
R26 = CMP-0026515-2: RES, 6.49 k, 1%, 0.063 W, AEC-Q200 Grade 0, 0402; Manufacturer: Vishay-Dale; Power_W: 63mW; TempCo: 100 ppm/C; Value_Code: 6k49; Value: 6.49k; EIA_Code: E96; SizeX_mm: 1; SizeY_mm: 0.5; SizeZ_mm: 0.6; Value2: 0.063W; AEC Qualified: Y; VDC_V: 50V; AEC Category: Q200; AEC Grade: 0
R28 R204-R206 = CMP-0026088-3: RES, 1.50 k, 1%, 0.063 W, AEC-Q200 Grade 0, 0402; Manufacturer: Vishay-Dale; Power_W: 63mW; TempCo: 100 ppm/C; Value_Code: 1k50; Value: 1.50k; EIA_Code: E96; Res_ohm: 1.5k; SizeX_mm: 1; SizeY_mm: 0.5; SizeZ_mm: 0.6; Value2: 0.063W; AEC Qualified: Y; VDC_V: 50V; AEC Category: Q200; AEC Grade: 0
R29-R32 R201 R207 = CMP-0026237-2: RES, 2.49 k, 1%, 0.063 W, AEC-Q200 Grade 0, 0402; Manufacturer: Vishay-Dale; Power_W: 63mW; TempCo: 100 ppm/C; Value_Code: 2k49; Value: 2.49k; EIA_Code: E96; SizeX_mm: 1; SizeY_mm: 0.5; SizeZ_mm: 0.6; Value2: 0.063W; AEC Qualified: Y; VDC_V: 50V; AEC Category: Q200; AEC Grade: 0
U9 = CMP-0124715-2: Deterministic, Low-Latency, Low-Power, 10/100 Mbps, Industrial Ethernet PHY; Manufacturer: Texas Instruments; SizeZ_mm: 1mm; AEC Qualified: No; Data Rate: 100Mbits/s; Interface: Ethernet,Other; Max Supply Voltage: 3.6V; Min Supply Voltage: 1.62V; Number Of Channels: 1; Simplex Duplex: Full-Duplex; Standoff Height: 0mm; TaMax_C: +85°C; TaMin_C: -40°C; AEC Category: Q200; CompType: IC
